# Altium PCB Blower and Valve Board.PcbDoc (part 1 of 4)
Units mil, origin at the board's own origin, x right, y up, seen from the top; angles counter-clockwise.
Board outline 4950 x 3450 mil, 4 copper layers (Top Layer, Signal Layer 1, Signal Layer 2, Bottom Layer), stack 64.4 mil thick; 260 components, 151 nets, 912 pads, 417 vias.
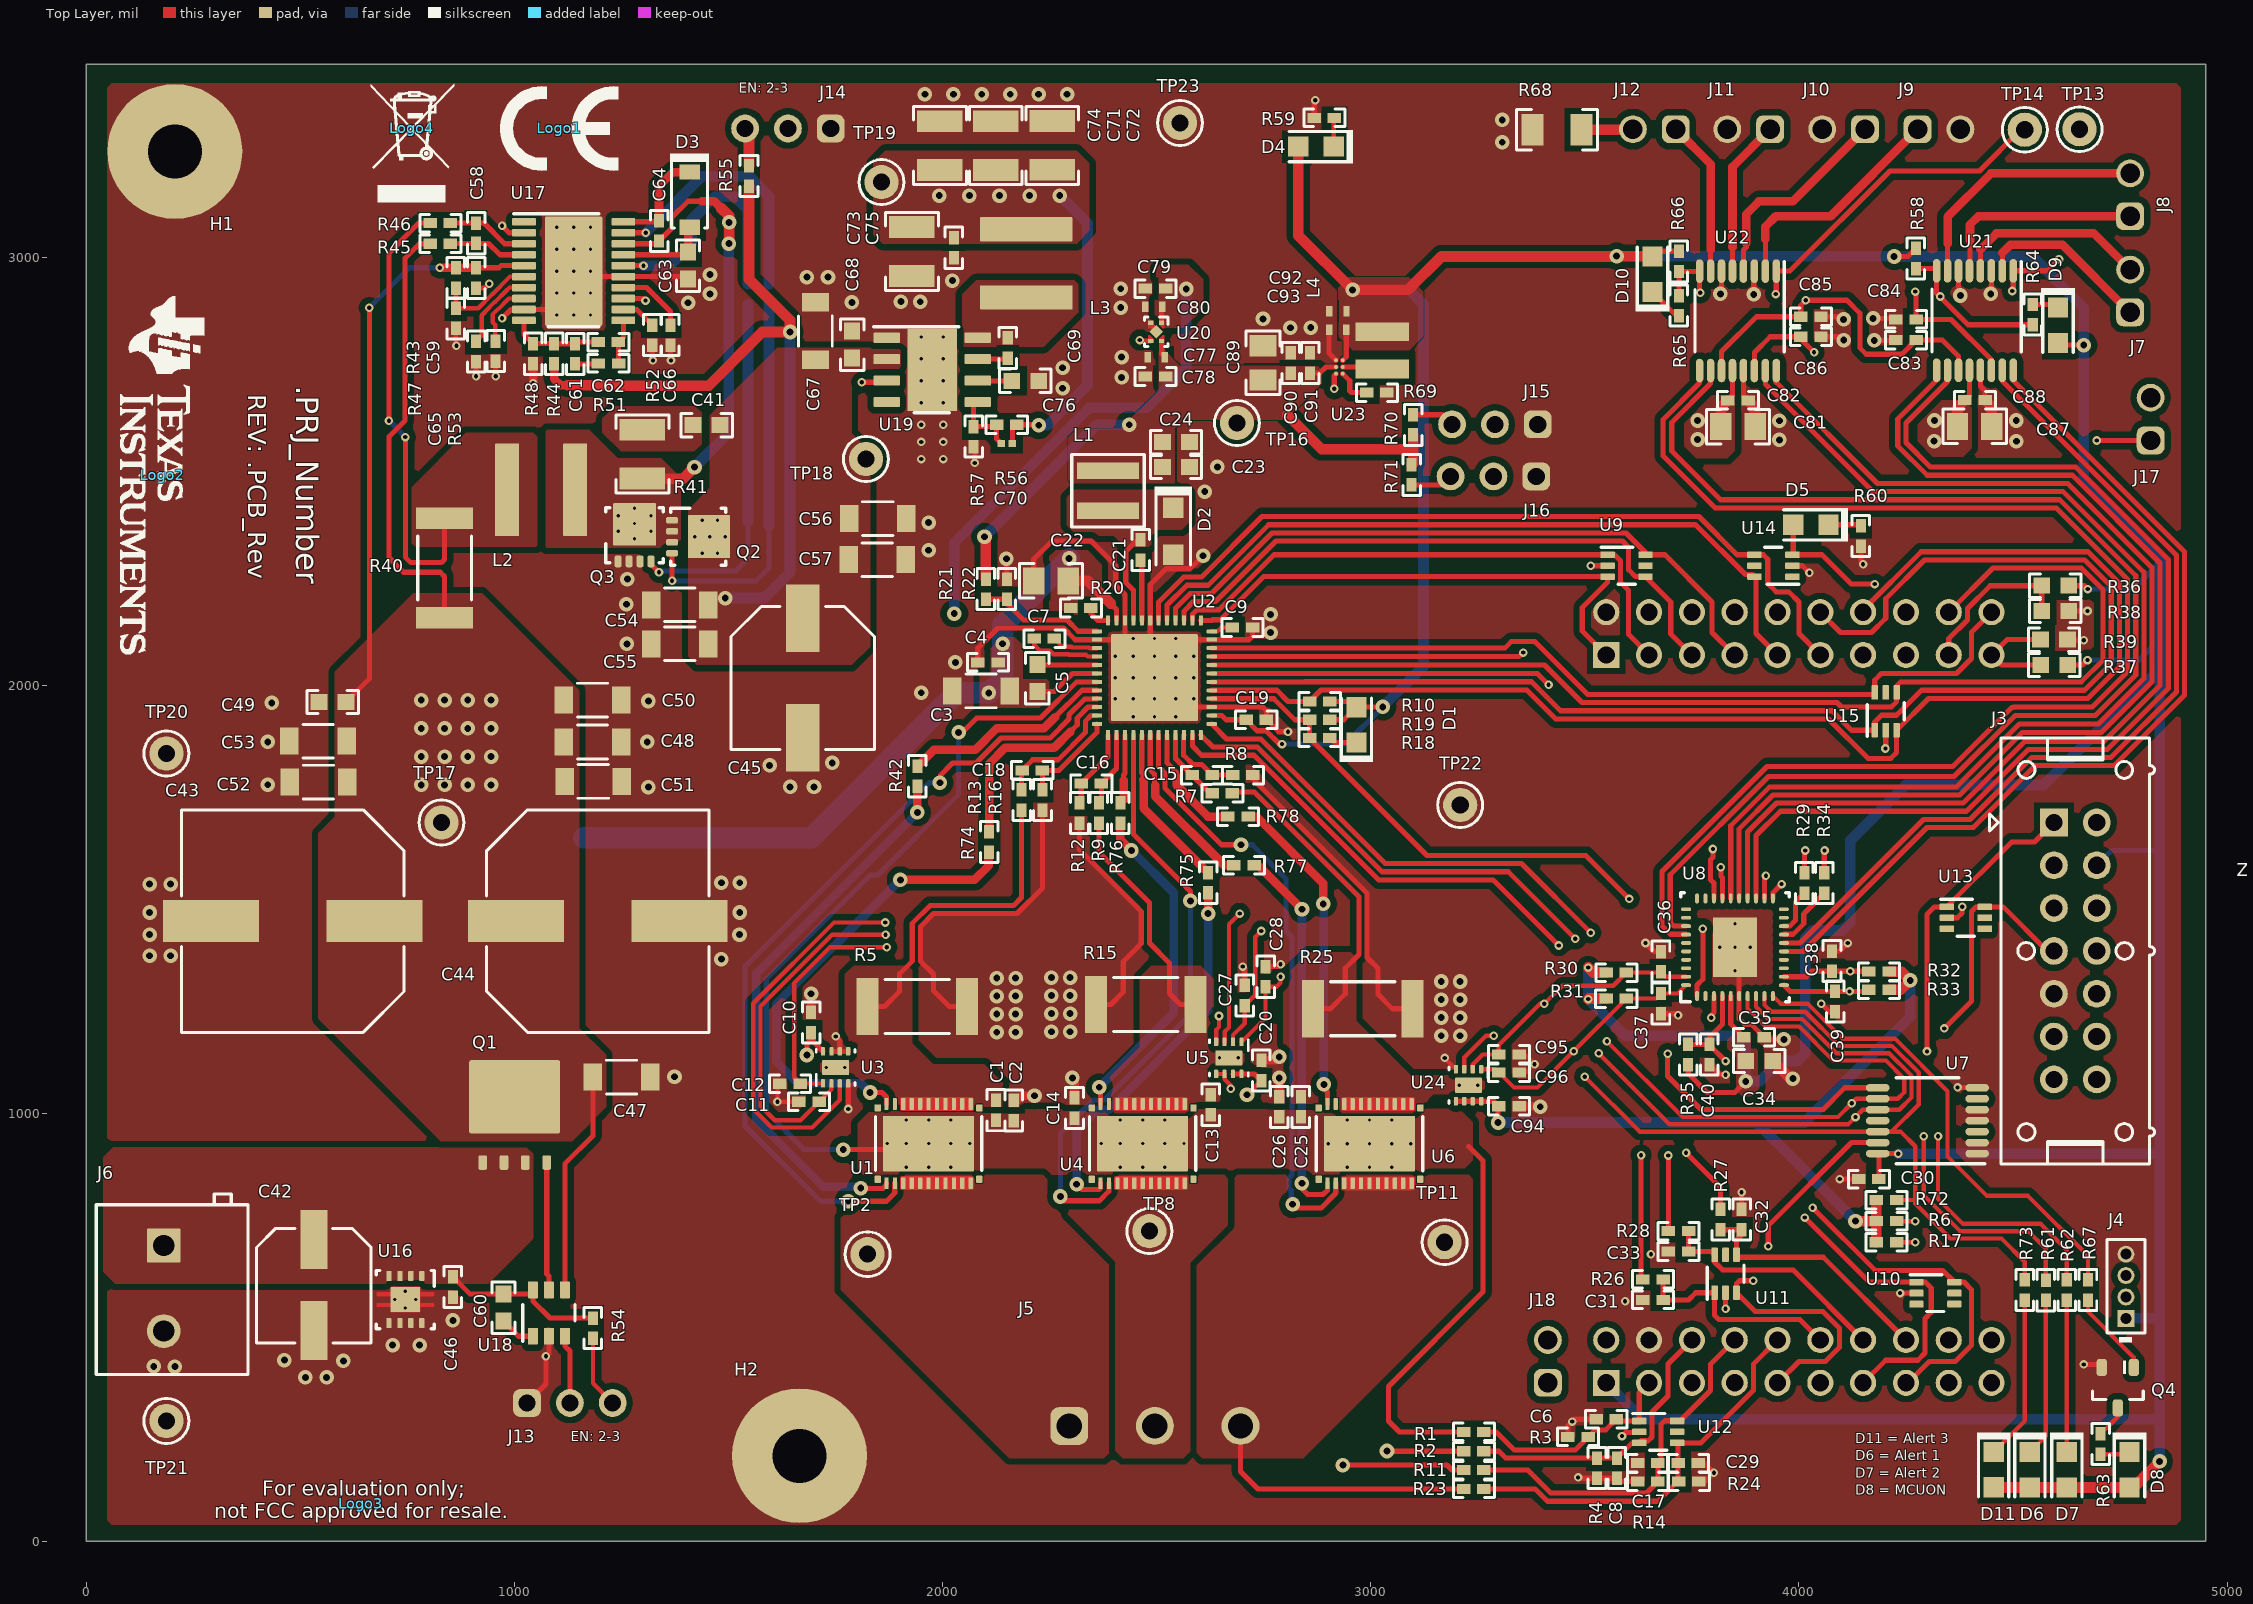
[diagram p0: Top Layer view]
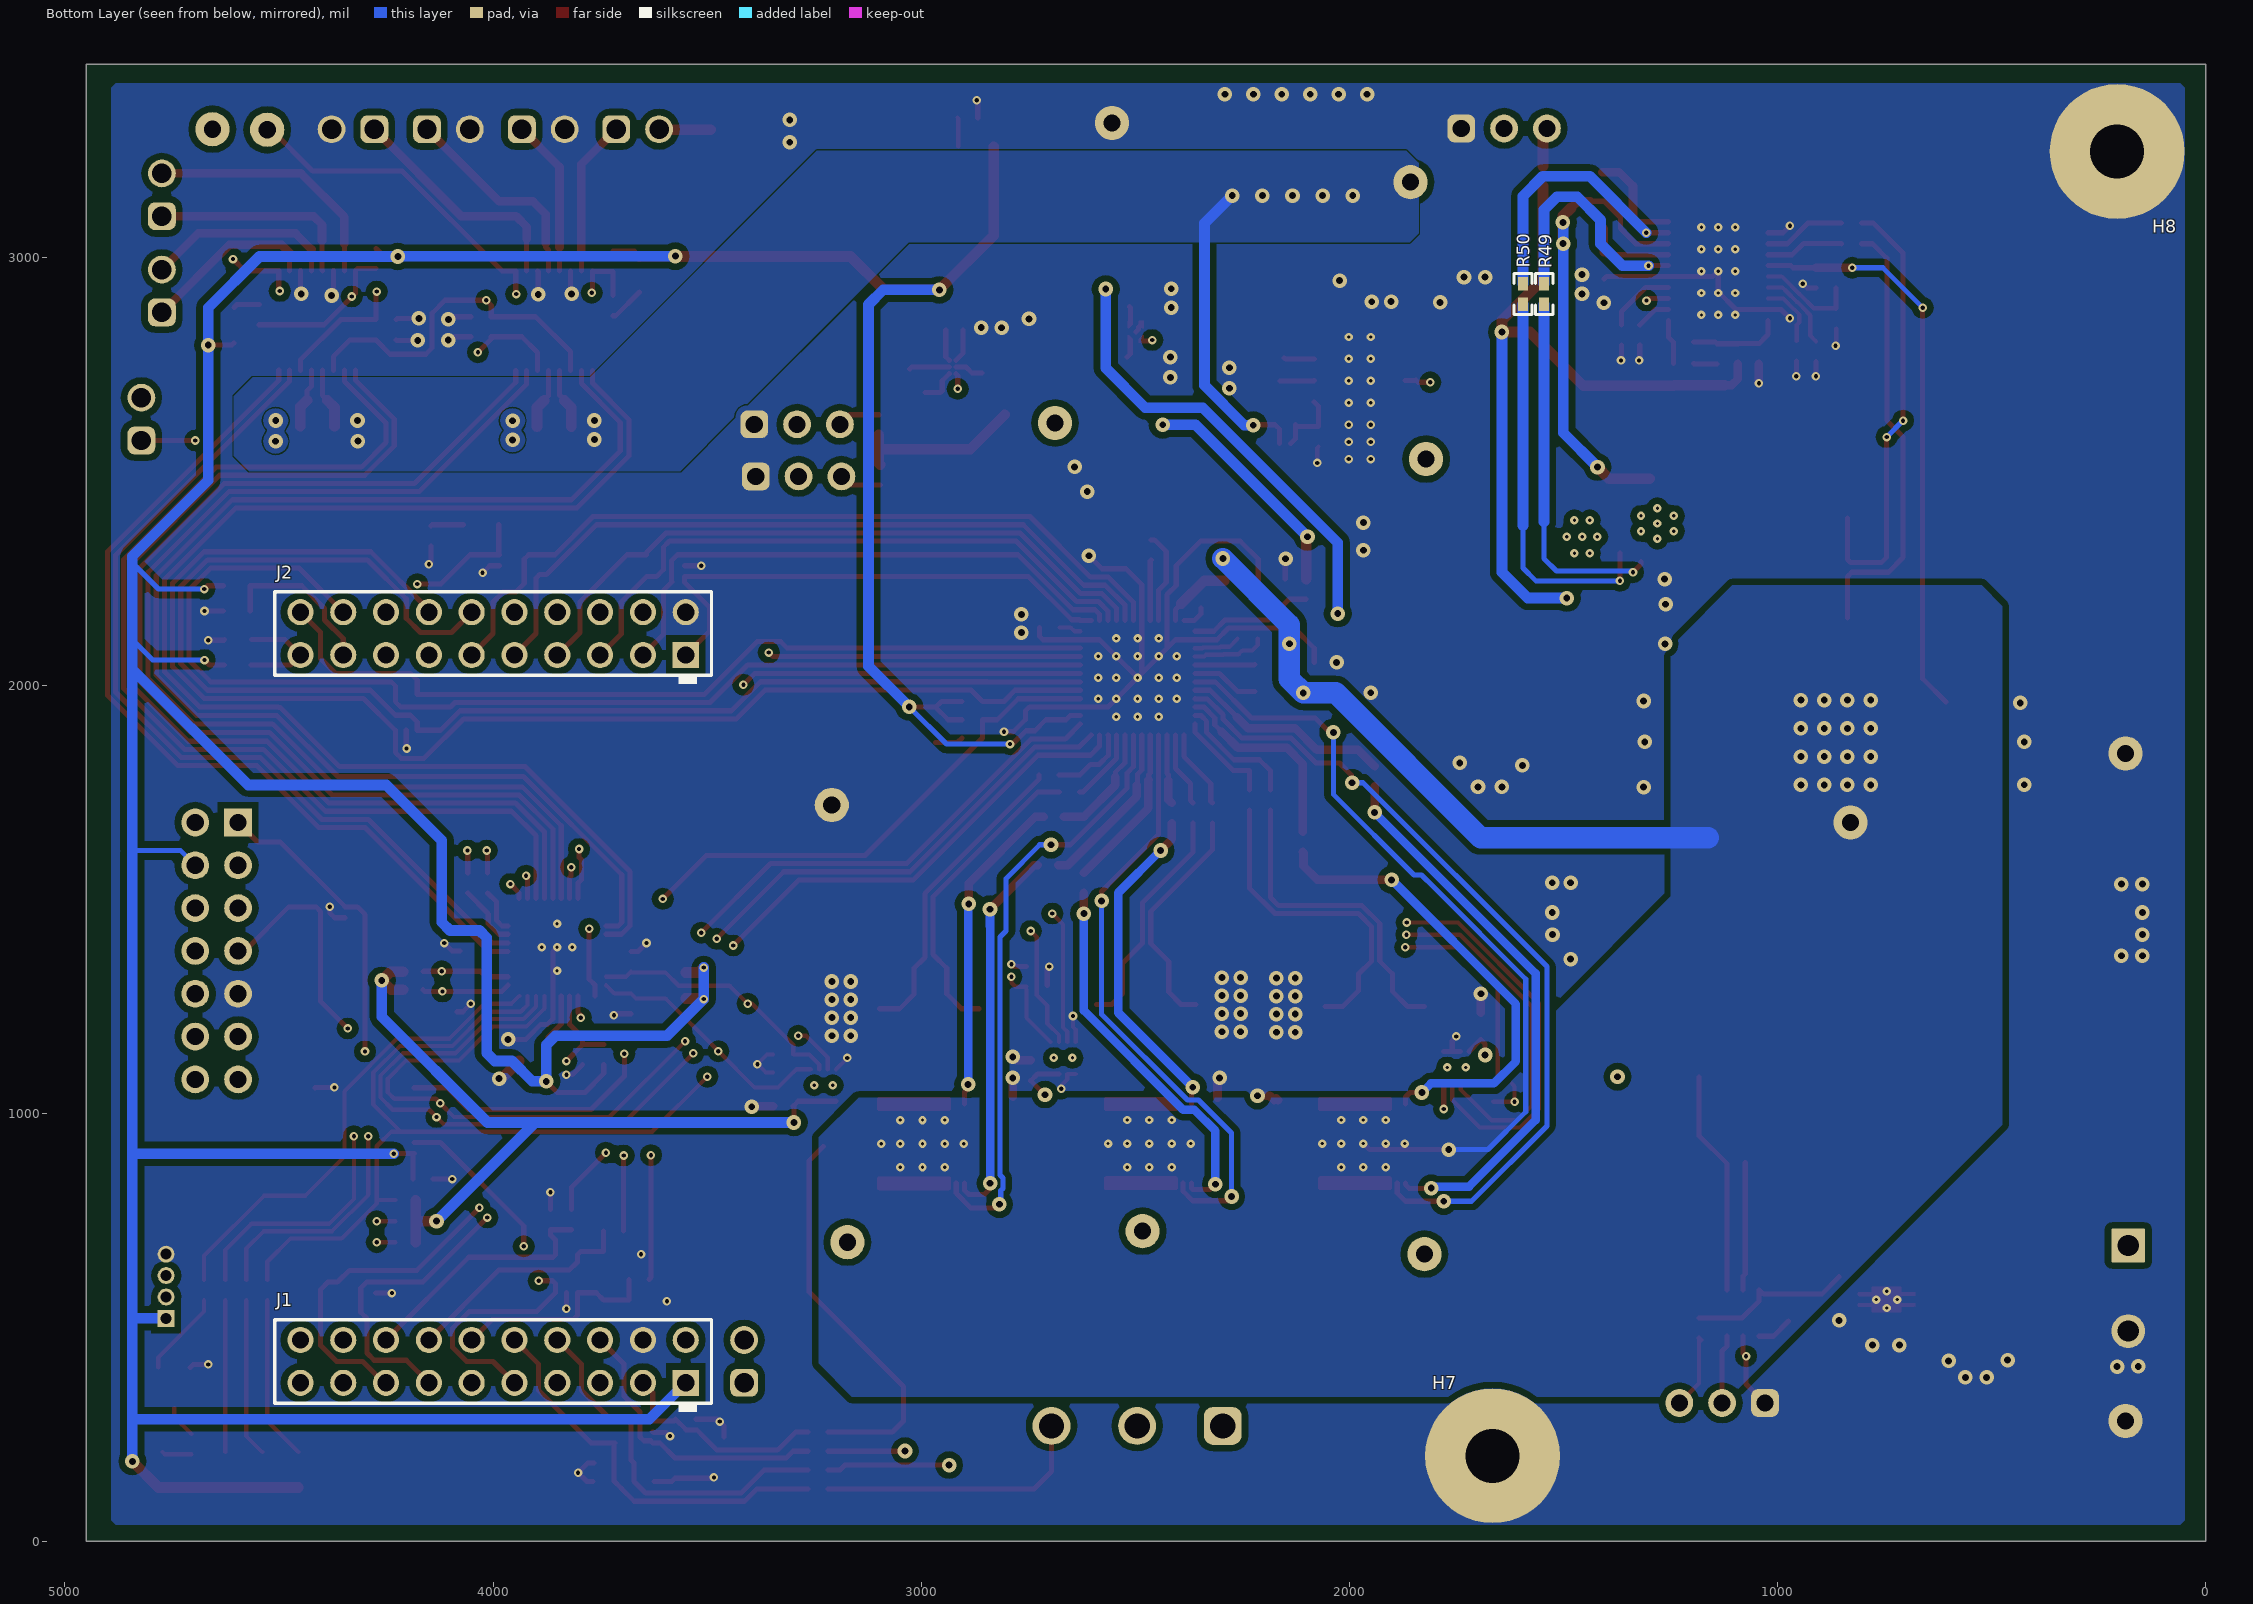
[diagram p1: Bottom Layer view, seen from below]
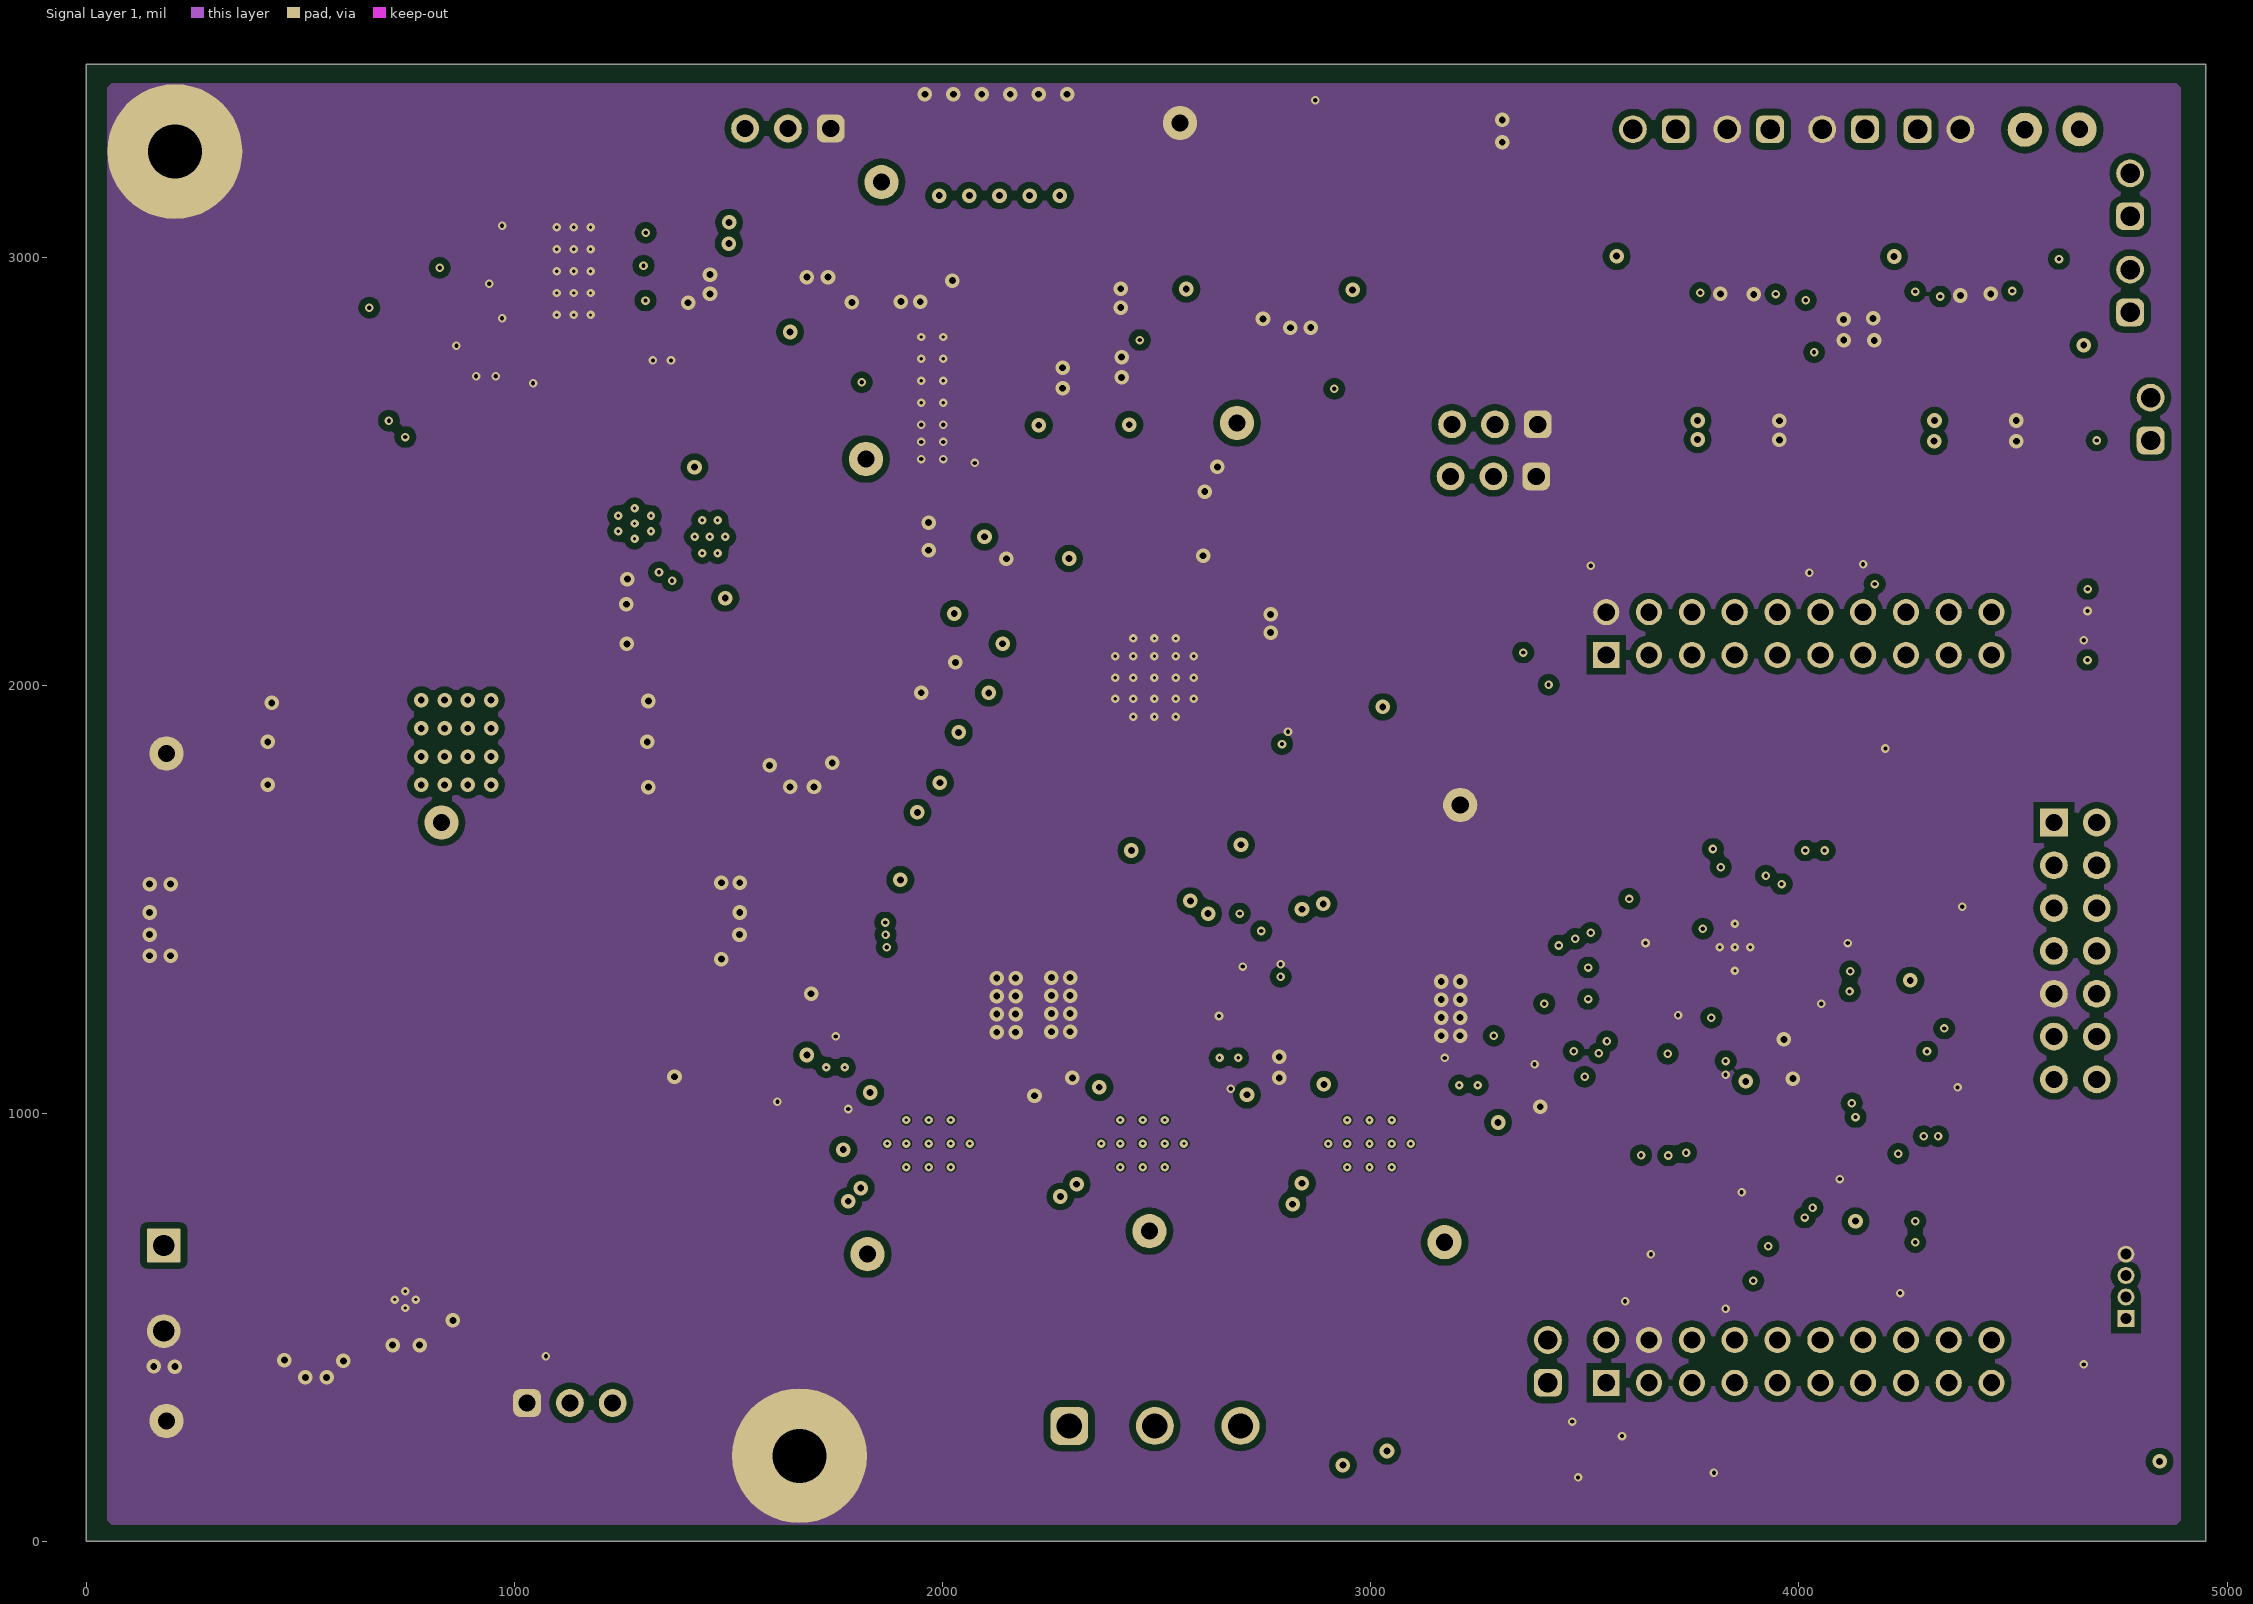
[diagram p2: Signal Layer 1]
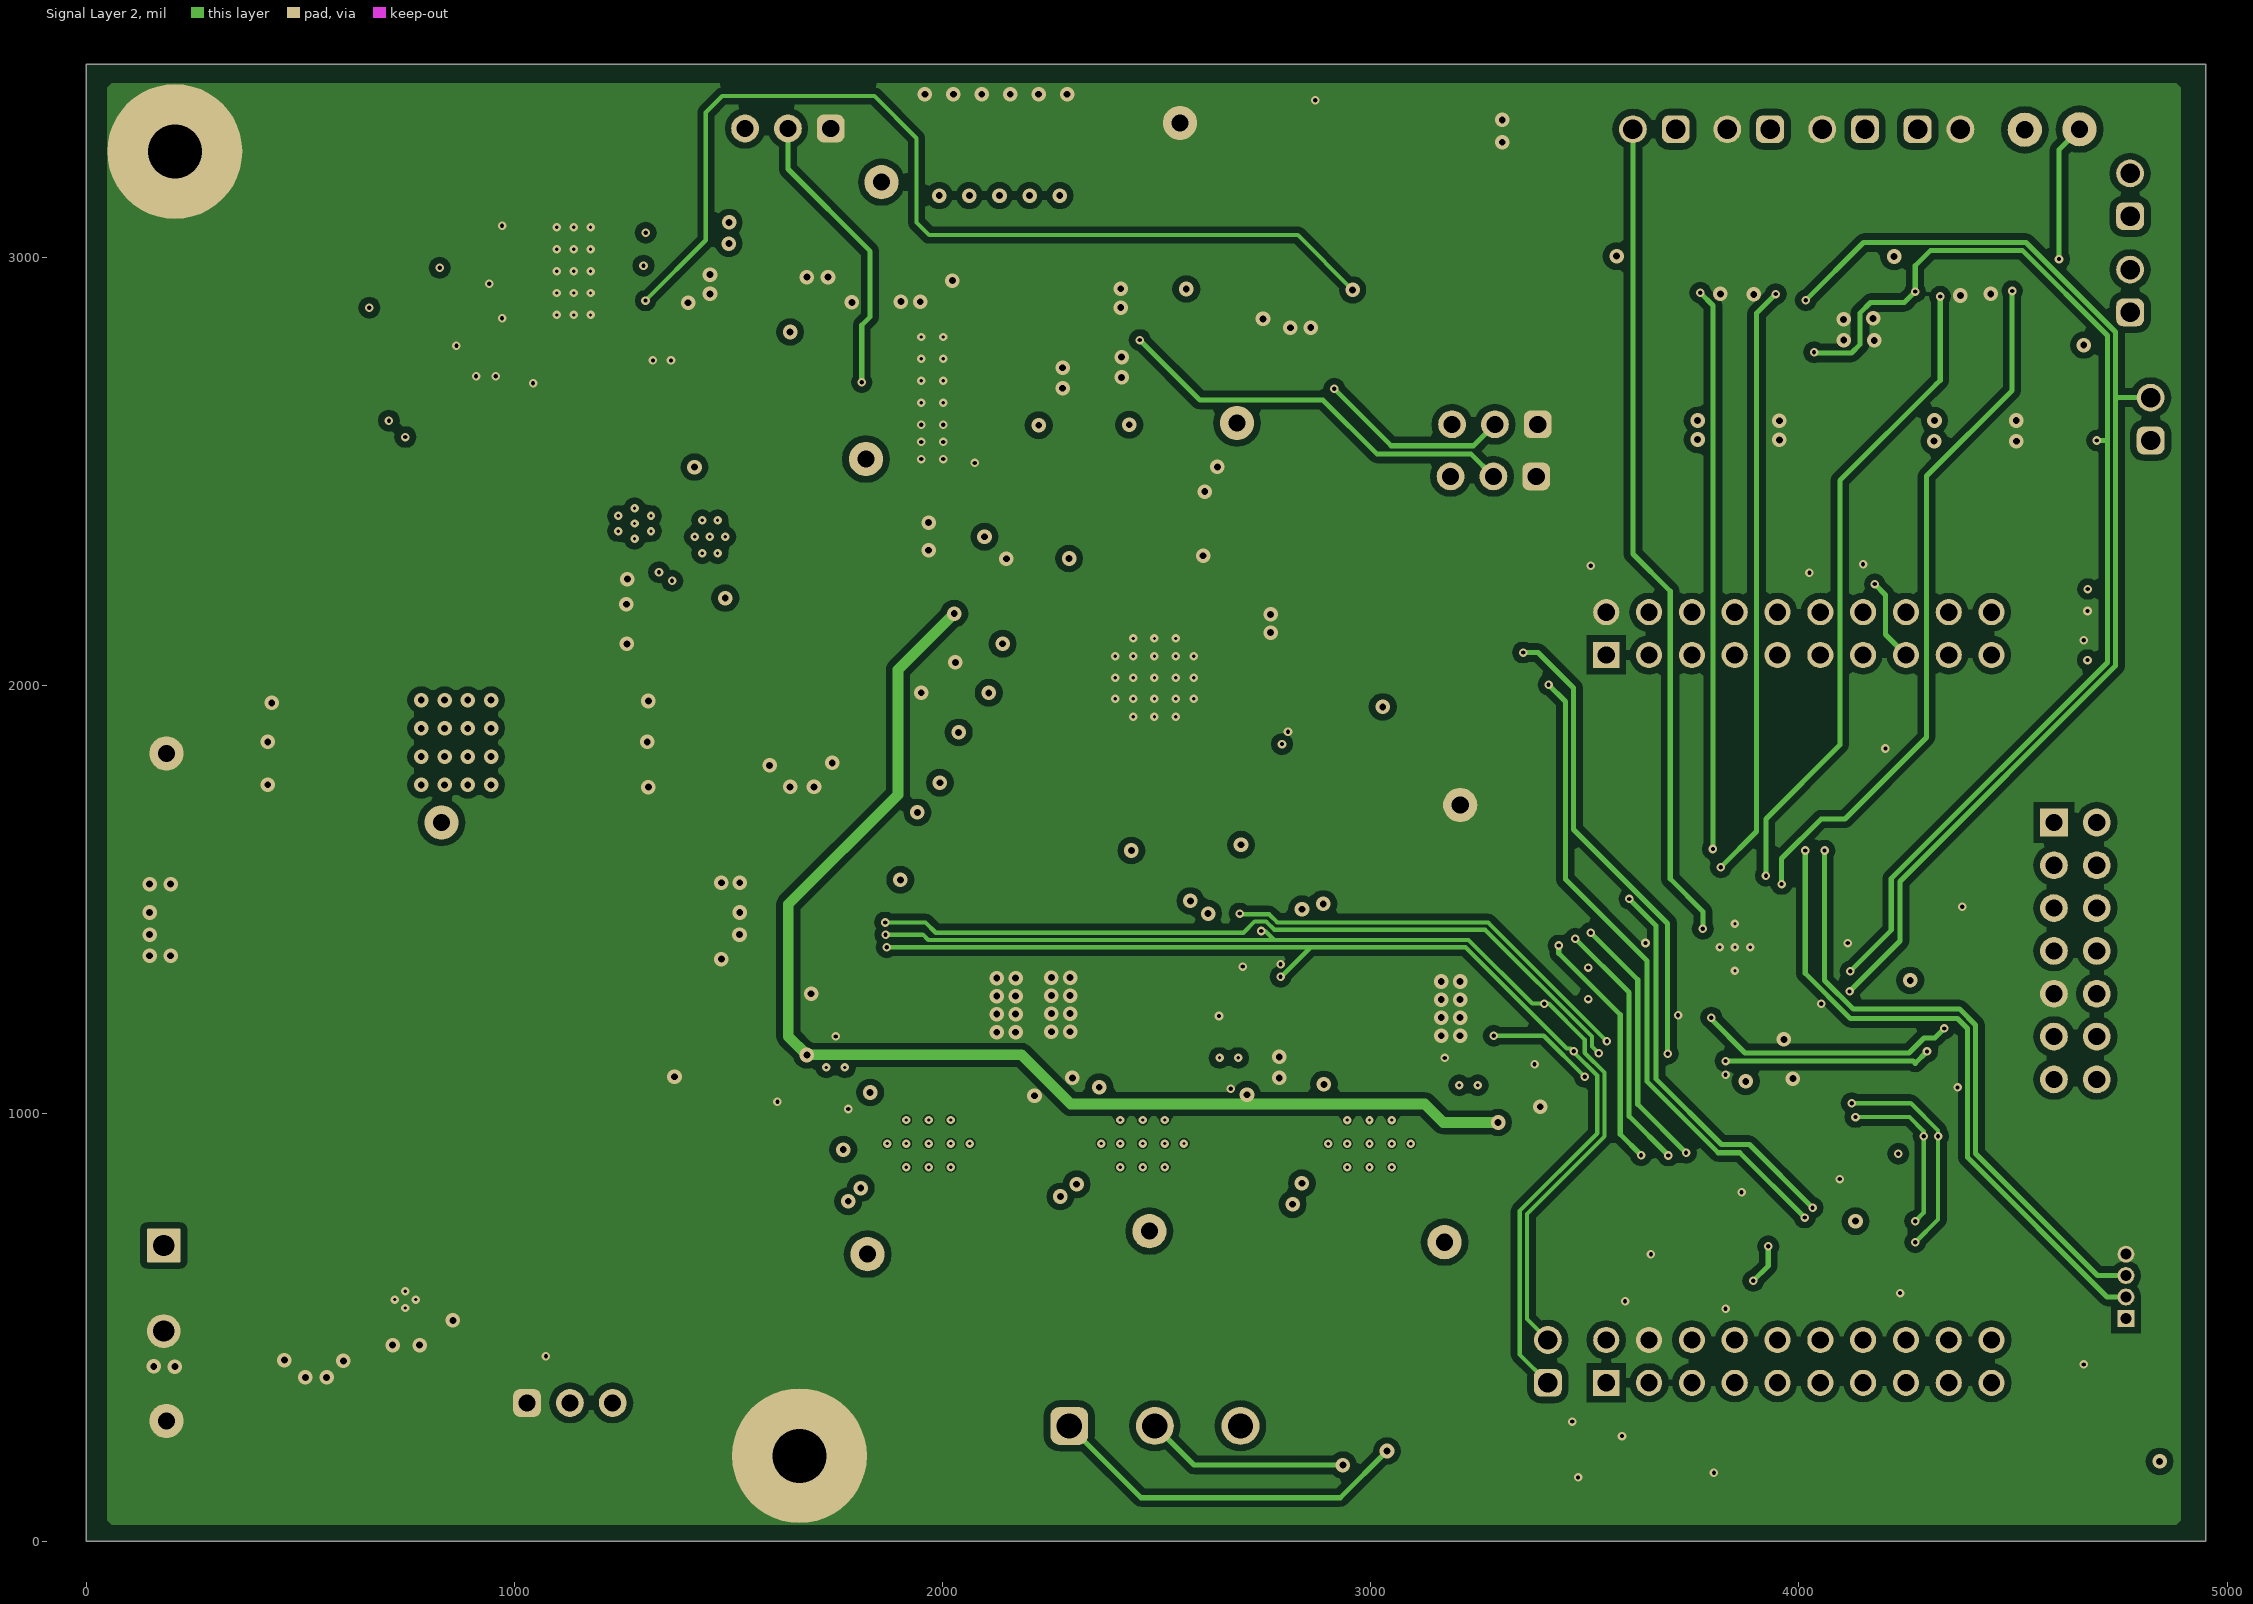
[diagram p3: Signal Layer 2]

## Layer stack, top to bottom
Top Solder: solder mask 0.4, Solder Resist, Dk 3.5
Top Layer: signal copper 2.8
Dielectric 1: prepreg 8, FR-4, Dk 4.2
Signal Layer 1: signal copper 1.4
Dielectric 2: core 40, FR-4, Dk 4.2
Signal Layer 2: signal copper 1.4
Dielectric 3: prepreg 8, FR-4, Dk 4.2
Bottom Layer: signal copper 2.8
Bottom Solder: solder mask 0.4, Solder Resist, Dk 3.5

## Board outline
0,0 4950,0 4950,3450 0,3450

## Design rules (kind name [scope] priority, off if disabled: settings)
AcuteAngle [All] p1: minimum=4.50000000000000E+0001 checktracksonly=FALSE
AssemblyTestPointUsage [All] p1: valid=2
BoardOutlineClearance BoardOutlineClearance_MountingHoles [OnCopper and InComponentClass('Mounting Holes')] p1: gap=40 ignorepadtopadclearanceinfootprint=FALSE
BoardOutlineClearance BoardOutlineClearance_Poly [OnCopper and InPoly] p2: gap=15 ignorepadtopadclearanceinfootprint=FALSE
BoardOutlineClearance [OnCopper and Not InComponentClass('Logo') and not InComponentClass('FiducialMark') and not InRegion(1000,500,4000,800)] p3: gap=15 ignorepadtopadclearanceinfootprint=FALSE
Clearance Clearance_Small_Packages [InComponent('U20') OR InComponent('U23') OR InComponent('U1') Or InComponent('U4') Or InComponent('U6') Or InRegionRelative(2880,2707,2964,2782)] p1: gap=3 ignorepadtopadclearanceinfootprint=FALSE
Clearance Clearance_Keepouts [((IsTrack Or IsArc) And Not InPoly) And IsFree and IsKeepOut vs ((IsTrack Or IsArc) And Not InPoly) And IsFree and IsKeepOut] p2: gap=0 ignorepadtopadclearanceinfootprint=FALSE
Clearance Clearance_Poly [InPolygon] p3: gap=15 ignorepadtopadclearanceinfootprint=FALSE except(0: Arc-Hole Track-Hole SMDPad-Hole THPad-Hole Via-Hole Fill-Hole Poly-Hole Region-Hole Text-Hole)
Clearance [All] p4: gap=7 ignorepadtopadclearanceinfootprint=FALSE
ComponentClearance ComponentClearance_MountingHoles_FiducialMarks [InComponentClass('Mounting Holes') vs InComponentClass('FiducialMark')] p1: gap=50 collisioncheckmode=3 verticalgap=10 showdistances=FALSE
ComponentClearance ComponentClearance_Shunt [InComponentClass('Header') vs InComponentClass('Shunt')] p2: gap=0 collisioncheckmode=3 verticalgap=0 showdistances=FALSE
ComponentClearance ComponentClearance_Logo [InComponentClass('Logo')] p3: gap=20 collisioncheckmode=3 verticalgap=10 showdistances=FALSE
ComponentClearance ComponentClearance_ScrewToNut [(HasFootprint('NY PMS 440 0025 PH')) vs (HasFootprint('Keystone_1902C'))] p4: gap=5 collisioncheckmode=3 verticalgap=10 showdistances=FALSE
ComponentClearance ComponentClearance_MountingHoles [InComponentClass('Mounting Holes')] p5: gap=250 collisioncheckmode=3 verticalgap=100000 showdistances=FALSE
ComponentClearance ComponentClearance_SmallPassives [HasFootprint('0201*') or HasFootprint('0402*') or HasFootprint('0508') or HasFootprint('0603*') or HasFootprint('0612') or HasFootprint('0805*') or HasFootprint('0815*') or HasFootprint('0830*') or HasFootprint('1206*') or HasFootprint('1210*') or HasFootprint('1808*') or HasFootprint('1812*') or HasFootprint('1825*') or HasFootprint('2010*') or HasFootprint('2220*') or HasFootprint('2225*') or HasFootprint('2512*') or HasFootprint('2728*') or HasFootprint('3518*') vs HasFootprint('0201*') or HasFootprint('0402*') or HasFootprint('0508') or HasFootprint('0603*') or HasFootprint('0612') or HasFootprint('0805*') or HasFootprint('0815*') or HasFootprint('0830*') or HasFootprint('1206*') or HasFootprint('1210*') or HasFootprint('1808*') or HasFootprint('1812*') or HasFootprint('1825*') or HasFootprint('2010*') or HasFootprint('2220*') or HasFootprint('2225*') or HasFootprint('2512*') or HasFootprint('2728*') or HasFootprint('3518*')] p6: gap=14.96 collisioncheckmode=3 verticalgap=10 showdistances=FALSE
ComponentClearance ComponentClearance_THtoSMT [IsThruComponent vs IsSMTComponent] p7: gap=20 collisioncheckmode=3 verticalgap=20 showdistances=FALSE
ComponentClearance ComponentClearance_THtoTH [IsThruComponent vs IsThruComponent] p8: gap=20 collisioncheckmode=3 verticalgap=20 showdistances=FALSE
ComponentClearance [All] p9: gap=10 collisioncheckmode=3 verticalgap=10 showdistances=FALSE
DiffPairsRouting [All] p1: maxlimit=100 minlimit=10 mostfreqgap=10 toplayer_minwidth=15 toplayer_maxwidth=15 toplayer_prefwidth=15 midlayer1_minwidth=15 midlayer1_maxwidth=15 midlayer1_prefwidth=15 midlayer2_minwidth=15 midlayer2_maxwidth=15 midlayer2_prefwidth=15 bottomlayer_minwidth=15 bottomlayer_maxwidth=15 bottomlayer_prefwidth=15 maxuncoupledlength=1000
FabricationTestPointUsage TestPointUsage [All] p1: valid=2 allowmultiple=FALSE
FabricationTestpoint Testpoint [All] p1: side=3 testpointundercomponent=TRUE minsize=40 maxsize=100 preferedsize=60 minholesize=0 maxholesize=40 preferedholesize=32 testpointgrid=1 allowsidetop=TRUE allowsidebottom=TRUE usegrid=TRUE gridtolerance=0.01
FanoutControl Fanout_LCC [IsLCC] p1: bgadir=Out bgaviamode=Centered fanoutstyle=Auto fanoutdirection=Alternating viagrid=1 // Fanout_LCC (Default Rule)
FanoutControl Fanout_BGA [IsBGA] p2: bgadir=Out bgaviamode=Centered fanoutstyle=Auto fanoutdirection=Alternating viagrid=1 // Fanout_BGA (Default Rule)
FanoutControl Fanout_Default [All] p4: bgadir=Out bgaviamode=Centered fanoutstyle=Auto fanoutdirection=Alternating viagrid=1 // Fanout_Default (Default Rule)
FanoutControl Fanout_Small [(CompPinCount < 5)] p5: bgadir=Out bgaviamode=Centered fanoutstyle=Auto fanoutdirection=OutThenIn viagrid=1 // Fanout_Small (Default Rule)
HoleSize [All] p1: absolutevalues=TRUE maxlimit=251 minlimit=5 maxpercent=80.000 minpercent=20.000
HoleToHoleClearance [All] p1: gap=7 allowstackedmicrovias=TRUE
MinimumAnnularRing MinimumAnnularRing_ThermalPadVias [IsVia and InAnyComponent] p1: minimumring=5.91
MinimumAnnularRing [All] p2: minimumring=1.5
MinimumSolderMaskSliver MinimumSolderMaskSliver_Logo [InComponentClass('Logo') vs InComponentClass('Logo')] p1: minsoldermaskwidth=0.7
MinimumSolderMaskSliver [All] p2: minsoldermaskwidth=3.94
PlaneClearance [All] p1: clearance=15
PlaneConnect [All] p1: planeconnectstyle=Direct reliefexpansion=10 reliefentries=4 reliefconductorwidth=10 reliefairgap=10
PolygonConnect [All] p1: connectstyle=Direct reliefconductorwidth=10 reliefentries=4 polygonreliefangle="90 Angle" airgapwidth=10
RoutingVias ThermalPadVias [IsVia and InAnyComponent] p1: holewidth=7.87 width=19.68 viastyle="Through Hole" minholewidth=7.87 minwidth=19.68 maxholewidth=12.99 maxwidth=23.62
RoutingVias [All] p2: holewidth=16 width=34 viastyle="Through Hole" minholewidth=6 minwidth=10 maxholewidth=40 maxwidth=65
SilkToBoardRegionClearance [Not ((IsComment or IsDesignator) And (Hide <> 'False')) and not InRegion(1000,500,4000,800)] p1:
SilkToSilkClearance SilkToSilkClearance_Pb-FreeLogo [(HasFootprint('Pb-Free_Overlay_Medium') OR HasFootprint('Pb-Free_Overlay_Small')) vs (HasFootprint('Pb-Free_Overlay_Medium') OR HasFootprint('Pb-Free_Overlay_Small'))] p1: silktosilkclearance=0
SilkToSilkClearance [All] p2: silktosilkclearance=0
SilkToSolderMaskClearance SilkToComponentPadClearance [IsPad and InAnycomponent] p1: minsilkscreentomaskgap=0 clearancetoexposedcopper=TRUE
SilkToSolderMaskClearance "Silk to Solder Mask Opening" [All] p2: minsilkscreentomaskgap=0 clearancetoexposedcopper=FALSE
SolderMaskExpansion [All] p1: expansion=1.97
Width [All] p1: maxlimit=100 minlimit=6 preferedwidth=10 checkconnectedcopper=TRUE
13 further rules are at their usual default settings.

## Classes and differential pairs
component class Logo: Logo2
component class "Mounting Holes": H1 H2
component class Header: J4 J7 J8 J9 J10 J11 J12 J13 J14 J15 J16 J17 J18
component class Hardware: !PCB H1 H2 H7 H8 Logo1 Logo2 Logo3 Logo4 ZZ1 ZZ2 ZZ3 ZZ4
component class AssemblyNote: ZZ1 ZZ2 ZZ3 ZZ4
component class "Valve Drivers and Fault Indicators": C81 C82 C83 C84 C85 C86 C87 C88 D4 D5 D6 D7 D8 D9 D10 D11 J7 J8 J9 J10 J11 J12 Q4 R58 R59 R60 R61 R62 R63 R64 R65 R66 R67 R68 R73 TP13 TP14 TP20 TP21 TP22 TP23 U21 U22
component class "Power Tree": C41 C42 C43 C44 C45 C46 C47 C48 C49 C50 C51 C52 C53 C54 C55 C56 C57 C58 C59 C60 C61 C62 C63 C64 C65 C66 C67 C68 C69 C70 C71 C72 C73 C74 C75 C76 C77 C78 C79 C80 C89 C90 C91 C92 C93 D3 J6 J13 J14 J15 J16 L2 L3 L4 Q1 Q2 Q3 R40 R41 R43 R44 R45 R46 R47 R48 R49 R50 R51 R52 R53 R54 R55 R56 R57 R69 R70 R71 TP17 TP18 TP19 U16 U17 U18 U19 U20 U23
component class "MCU and Connectors": C34 C35 C36 C37 C38 C39 C40 J1 J2 J3 J4 J5 J17 J18 R29 R30 R31 R32 R33 R34 R35 R36 R37 R38 R39 U8 U9 U10 U11 U12 U13 U14 U15
component class "BLDC Motor Driver and TMP Sensors": C1 C2 C3 C4 C5 C6 C7 C8 C9 C10 C11 C12 C13 C14 C15 C16 C17 C18 C19 C20 C21 C22 C23 C24 C25 C26 C27 C28 C29 C30 C31 C32 C33 C94 C95 C96 D1 D2 L1 R1 R2 R3 R4 R5 R6 R7 R8 R9 R10 R11 R12 R13 R14 R15 R16 R17 R18 R19 R20 R21 R22 R23 R24 R25 R26 R27 R28 R42 R72 R74 R75 R76 R77 R78 TP2 TP8 TP11 TP16 U1 U2 U3 U4 U5 U6 U7 U24

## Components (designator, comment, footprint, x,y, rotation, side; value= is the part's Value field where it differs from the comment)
C1 "C1005X7R1H104K050BB" 0402 2124.66,1007.23 r90 top value=0.1uF
C2 "GRM155R71H103KA88D" 0402 2165.99,1006.38 r90 top value=0.01uF
C3 "CL31B106KBHNNNE" 1206_180 2089.75,1986.66 r180 top value=10uF
C4 "C1005X7R1H104K050BB" 0402 2105.79,2052.99 r180 top value=0.1uF
C5 "UMK107AB7105KA-T" 0603 2221.11,2016.51 r90 top value=1uF
C6 "885012105001" 0402 3550,285.43 r180 top value=0.1uF
C7 "C1005X7R1H473K050BB" 0402 2237.55,2108.58 r0 top value=0.047uF
C8 "885012105001" 0402 3575,171.07 r270 top value=0.1uF
C9 "GRM155R70J105MA12D" 0402 2700.22,2134.68 r0 top value=1uF
C10 "GRM155R71E103KA01D" 0402 1692.91,1211.85 r90 top value=0.01uF
C11 "885012005009" 0402 1687.69,1026.98 r180 top value=22pF
C12 "885012005009" 0402 1643.7,1069.07 r180 top value=22pF
C13 "C1005X7R1H104K050BB" 0402 2626.23,1019.86 r90 top value=0.1uF
C14 "GRM155R71H103KA88D" 0402 2308.06,1012.25 r90 top value=0.01uF
C15 "GRM155R61E102KA01D" 0402 2606.23,1789.88 r0 top value=1000pF
C16 "GRM155R61E102KA01D" 0402 2347.24,1770.17 r180 top value=1000pF
C17 "885012105001" 0402 3647.13,182.88 r180 top value=0.1uF
C18 "GRM155R61E102KA01D" 0402 2209.3,1801.02 r0 top value=1000pF
C19 "885012105010" 0402 2732.53,1919.13 r0 top value=0.1uF
C20 "GRM155R71E103KA01D" 0402 2744.34,1099.78 r90 top value=0.01uF
C21 "160R07X104KV4T" 0402_065 2462.58,2315.77 r90 top value=0.1uF
C22 "C2012X5R1H475K125AB" 0805_HV 2252.96,2243.67 r180 top value=4.7uF
C23 "C1608X5R1A226M080AC" 0603 2545.13,2509.38 r0 top value=22uF
C24 "C1608X5R1A226M080AC" 0603 2545.13,2567.37 r0 top value=22uF
C25 "C1005X7R1H104K050BB" 0402 2836.76,1015.13 r90 top value=0.1uF
C26 "GRM155R71H103KA88D" 0402 2786.16,1015.13 r90 top value=0.01uF
C27 "885012005009" 0402 2705.61,1275.27 r90 top value=22pF
C28 "885012005009" 0402 2754.18,1319.03 r90 top value=22pF
C29 "885012105001" 0402 3741.38,182.88 r0 top value=0.1uF
C30 "885012105001" 0402 4163.39,846.46 r180 top value=0.1uF
C31 "GRM155R61C222KA01D" 0402 3659.34,564.06 r180 top value=2200pF
C32 "GRM155R61C222KA01D" 0402 3866.09,751.75 r90 top value=2200pF
C33 "GRM155R61C222KA01D" 0402 3718.74,677.17 r180 top value=2200pF
C34 "CL10A106MQ8NNNC" 0603 3907.48,1122.05 r0 top value=10uF
C35 "885012105010" 0402 3895.06,1177.66 r0 top value=0.1uF
C36 "885012005009" 0402 3677.81,1354.21 r90 top value=22pF
C37 "885012005009" 0402 3677.81,1256.2 r270 top value=22pF
C38 "885012005009" 0402 4077.25,1355.42 r90 top value=22pF
C39 "885012005009" 0402 4084.65,1260.95 r270 top value=22pF
C40 "GRM155R61C102KA01D" 0402 3790.76,1137.4 r270 top value=1000pF
C41 "GRM188R72A471KA01D" 0603 1448.82,2607.16 r180 top value=470pF
C42 "EMZA500ADA470MF80G" CAPSMT_62_F80 531.5,598.86 r270 top value=47uF
C43 "EMVA500ATR331MKE0S" CAPSMT_62_KE0 482.16,1448.95 r180 top value=330uF
C44 "EMVA500ATR331MKE0S" CAPSMT_62_KE0 1194.76,1448.95 r0 top value=330uF
C45 "EEE-FK1H181SP" SM_RADIAL_F 1673.23,2016.51 r270 top value=180uF
C46 "C1005X7R1H104K050BB" 0402 856.3,594.49 r270 top value=0.1uF
C47 "CL31B106KBHNNNE" 1206_180 1250,1084.65 r0 top value=10uF
C48 "CL31B106KBHNNNE" 1206_180 1182.17,1867.31 r0 top value=10uF
C49 "UMK107AB7105KA-T" 0603 575.28,1960.63 r180 top value=1uF
C50 "UMK316BBJ106KL-T" 1206_190 1182.17,1965.15 r0 top value=10uF
C51 "UMK316BBJ106KL-T" 1206_190 1183.91,1775.19 r0 top value=10uF
C52 "UMK316BBJ106KL-T" 1206_190 542.16,1773.62 r180 top value=10uF
C53 "UMK316BBJ106KL-T" 1206_190 541.22,1869.09 r180 top value=10uF
C54 "UMK316BBJ106KL-T" 1206_190 1385.91,2187.66 r180 top value=10uF
C55 "UMK316BBJ106KL-T" 1206_190 1385.91,2096.67 r180 top value=10uF
C56 "UMK316BBJ106KL-T" 1206_190 1848.55,2388.99 r0 top value=10uF
C57 "UMK316BBJ106KL-T" 1206_190 1847.18,2292.98 r0 top value=10uF
C58 "885012205055" 0402 910.3,3055.51 r270 top value=100pF
C59 "GRM155R61H104ME14D" 0402 910.25,2951.22 r270 top value=0.1uF
C60 "UMK107AB7105KA-T" 0603 974.41,546.1 r270 top value=1uF
C61 "GRM155R61A333KA01D" 0402 1141.7,2773.81 r270 top value=0.033uF
C62 "GRM155R71H561KA01D" 0402 1219.2,2801.12 r0 top value=560pF
C63 "EMK107BBJ106MA-T" 0603 1405.39,2979.85 r270 top value=10uF
C64 "C1005X5R1H104K050BB" 0402 1337.59,3061.02 r90 top value=0.1uF
C65 "C1005X5R1A104K050BA" 0402 910.25,2779.31 r270 top value=0.1uF
C66 "C1005X5R1A334K050BB" 0402 1364.11,2817.47 r270 top value=0.33uF
C67 "CL31B106KBHNNNE" 1206_180 1702.86,2827.1 r90 top value=10uF
C68 "C1608X7R1H224K080AB" 0603 1788.61,2795.46 r90 top value=0.22uF
C69 "C1005X7R1H104K050BB" 0402 2151.97,2787.7 r90 top value=0.1uF
C70 "GRM033R71E221KA01D" 0201 2149.77,2564.44 r180 top value=220pF
C71 "GRT32ER61E226KE13L" 1210_270 2124.08,3260.03 r90 top value=22uF
C72 "GRT32ER61E226KE13L" 1210_270 2255.97,3260.85 r90 top value=22uF
C73 "GRT32ER61E226KE13L" 1210_270 1928.09,3012.57 r270 top value=22uF
C74 "GRT32ER61E226KE13L" 1210_270 1993.57,3260.03 r90 top value=22uF
C75 "GRM155R61E105KA12D" 0402 2026.23,3021.65 r270 top value=1uF
C76 "CC0603MRX5R7BB105" 0603 2192.98,2710.82 r0 top value=1uF
C77 "CC0402MRX5R6BB106" 0402_070 2498.83,2766.14 r180 top value=10uF
C78 "GRM155R61A105KE15D" 0402 2497.38,2720.89 r180 top value=1uF
C79 "GRM155R61A105KE15D" 0402 2497.38,2926.14 r180 top value=1uF
C80 "CC0402MRX5R6BB106" 0402_070 2493.19,2883.86 r180 top value=10uF
C81 "GRM21BR61E226ME44L" 0805_HV 3857.63,2603.78 r0 top value=22uF
C82 "GRM155R71E104KE14D" 0402 3857.63,2665 r0 top value=0.1uF
C83 "885012005009" 0402 4250,2806 r180 top value=22pF
C84 "885012005009" 0402 4250,2854.33 r180 top value=22pF
C85 "885012005009" 0402 4027.97,2860.54 r0 top value=22pF
C86 "885012005009" 0402 4027.97,2813.74 r0 top value=22pF
C87 "GRM21BR61E226ME44L" 0805_HV 4410.51,2604.46 r0 top value=22uF
C88 "GRM155R71E104KE14D" 0402 4411.14,2665.68 r0 top value=0.1uF
C89 "C2012X5R1A476M125AC" 0805_HV 2748.27,2752.72 r90 top value=47uF
C90 "C1005X5R1A475K050BC" 0402_065 2813.14,2752.37 r90 top value=4.7uF
C91 "885012105010" 0402 2858.38,2752.37 r90 top value=0.1uF
C92 "CC0402MRX5R6BB106" 0402_070 2923.34,2873.58 r180 top value=10uF
C93 "CC0402MRX5R6BB106" 0402_070 2922.63,2829.85 r180 top value=10uF
C94 "GRM155R71E103KA01D" 0402 3322.64,1016.53 r0 top value=0.01uF
C95 "885012005009" 0402 3322.64,1137.4 r0 top value=22pF
C96 "885012005009" 0402 3322.64,1095.08 r0 top value=22pF
D1 "LTST-C170KRKT" LED_LTST-C170_Red 2966.39,1907.13 r270 top value=Red
D2 "PMEG6010CEH,115" SOD-123F 2538.44,2359.46 r270 top value=60V
D3 "MBR1H100SFT3G" SOD-123FL 1408.95,3134.02 r270 top value=100V
D4 "LTST-C171GKT" LED_LTST-C171 2871.98,3257.87 r0 top value=Green
D5 "LTST-C171GKT" LED_LTST-C171 4027.97,2374.61 r0 top value=Green
D6 "LTST-C170KRKT" LED_LTST-C170_Red 4539.37,167.32 r90 top value=Red
D7 "LTST-C170KRKT" LED_LTST-C170_Red 4625.67,167.32 r90 top value=Red
D8 "LTST-C171GKT" LED_LTST-C171 4772.36,167.32 r90 top value=Green
D9 "LTST-C170KRKT" LED_LTST-C170_Red 4605.3,2840.48 r90 top value=Red
D10 "LTST-C170KRKT" LED_LTST-C170_Red 3658.09,2959.82 r270 top value=Red
D11 "LTST-C170KRKT" LED_LTST-C170_Red 4454.95,167.68 r90 top value=Red
H1 "NY PMS 440 0025 PH" "NY PMS 440 0025 PH" 206.69,3246.49 r0 top
H2 "NY PMS 440 0025 PH" "NY PMS 440 0025 PH" 1665.51,200.05 r0 top
H7 "1902C" Keystone_1902C 1666.03,200.05 r180 bottom
H8 "1902C" Keystone_1902C 206.69,3246.49 r0 bottom
J1 "SSQ-110-03-G-D" Samtec_SSQ-110-03-x-D 4000,420.47 r0 bottom
J2 "SSQ-110-03-G-D" Samtec_SSQ-110-03-x-D 4000,2120.47 r0 bottom
J3 "SBH11-PBPC-D07-ST-BK" CONN_SBH11-PBPC-D07-ST-BK 4645.67,1379.23 r270 top
J4 "850-10-004-10-001101" Preci-dip_850-xx-004-10-001101 4763.78,595.97 r90 top
J5 "691236510003" Wurth_691236510003 2495.7,269.86 r0 top
J6 "ED120/2DS" On-Shore_ED120_2DS 180.71,591.18 r270 top
J7 "61300211121" WURTH_61300211121 4773.62,2920.65 r90 top
J8 "61300211121" WURTH_61300211121 4773.62,3145.4 r90 top
J9 "61300211121" WURTH_61300211121 4327.26,3298.45 r0 top
J10 "61300211121" WURTH_61300211121 4104.36,3298.45 r180 top
J11 "61300211121" WURTH_61300211121 3882.77,3298.45 r180 top
J12 "61300211121" WURTH_61300211121 3662.34,3298.45 r180 top
J13 "TSW-103-07-G-S" TSW-103-07-G-S 1129.34,323.43 r0 top
J14 "TSW-103-07-G-S" TSW-103-07-G-S 1638.59,3300.18 r180 top
J15 "TSW-103-07-G-S" TSW-103-07-G-S 3289.88,2609.24 r180 top
J16 "TSW-103-07-G-S" TSW-103-07-G-S 3286.47,2487.5 r180 top
J17 "61300211121" WURTH_61300211121 4821.51,2621.5 r90 top
J18 "61300211121" WURTH_61300211121 3413.61,420.47 r90 top
L1 "74438356220" WE-MAPI_4020 2386.38,2454.1 r90 top value=22uH
L2 "XAL6060-472MEB" XAL6060 1062.2,2456.3 r0 top value=4.7uH
L3 "XAL6060-333MEB" XAL6060 2195.44,2985.26 r90 top value=33uH
L4 "XFL3012-222MEB" XFL3012 3026.79,2781.74 r90 top value=2.2uH
Logo1 "CE Mark" CE_Mark_5mm 1104.33,3300.18 r0 top
Logo2 "Texas Instruments" TI_Stacked_Overlay_Small 177.17,2490.16 r270 top
Logo3 "FCC disclaimer" FCC_disclaimer_stacked 640.45,88.58 r0 top
Logo4 "WEEE logo" WEEE_Minimum 759.84,3300.18 r0 top
Q1 "CSD18532Q5B" DNK0008A 1000.49,996.06 r90 top value=60V
Q2 "CSD18543Q3A" DNH0008A 1429.03,2346.66 r0 top value=60V
Q3 "CSD18543Q3A" DNH0008A 1280.39,2350.1 r90 top value=60V
Q4 "BC847CLT1G" SOT-23 4744.8,359.15 r270 top value="45 V"
R1 "RC0402FR-0782KL" 0402 3240.75,255.87 r180 top value=82.0k
R2 "RC0402FR-0782KL" 0402 3240.75,210.6 r180 top value=82.0k
R3 "CRCW04024K99FKED" 0402 3484.25,244.09 r0 top value=4.99k
R4 "CRCW04024K99FKED" 0402 3528.35,171.07 r90 top value=4.99k
R5 "CRA2512-FZ-R010ELF" 2512 1940.47,1249.42 r180 top value=0.01
R6 "CRCW04025K10JNED" 0402 4204.51,748.03 r180 top value=5.1k
R7 "RK73H1ETTP10R0F" 0402 2653.23,1747.44 r180 top value=10.0
R8 "RK73H1ETTP10R0F" 0402 2701.23,1789.88 r180 top value=10.0
R9 "RK73H1ETTP10R0F" 0402 2364.96,1701.27 r90 top value=10.0
R10 "CRCW040210K0FKED" 0402 2880.75,1962.04 r0 top value=10.0k
R11 "RC0402FR-0782KL" 0402 3240.75,166.62 r180 top value=82.0k
R12 "RK73H1ETTP10R0F" 0402 2319.68,1701.27 r90 top value=10.0
R13 "RK73H1ETTP10R0F" 0402 2184.3,1731.92 r90 top value=10.0
R14 "CRCW04024K99FKED" 0402 3647.13,139.95 r0 top value=4.99k
R15 "CRA2512-FZ-R010ELF" 2512 2474.66,1254.11 r0 top value=0.01
R16 "RK73H1ETTP10R0F" 0402 2233.23,1731.92 r90 top value=10.0
R17 "CRCW04025K10JNED" 0402 4204.51,698.82 r180 top value=5.1k
R18 "CRCW0402470RJNED" 0402 2880.75,1876.74 r0 top value=470
R19 "CRCW040210K0FKED" 0402 2880.75,1919.13 r0 top value=10.0k
R20 "RMCF0402FT100K" 0402 2322.83,2180.26 r180 top value=100k
R21 "CRCW040249K9FKED" 0402 2101.03,2224.25 r90 top value=49.9k
R22 "CRCW040211K8FKED" 0402 2149.89,2224.25 r270 top value=11.8k
R23 "RC0402FR-0782KL" 0402 3240.75,122.63 r180 top value=82.0k
R24 "CRCW04024K99FKED" 0402 3742.76,139.95 r180 top value=4.99k
R25 "CRA2512-FZ-R010ELF" 2512 2980.96,1244.27 r180 top value=0.01
R26 "CRCW040256R2FKED" 0402 3659.34,612.11 r0 top value=56.2
R27 "CRCW040256R2FKED" 0402 3816.93,751.75 r270 top value=56.2
R28 "CRCW040256R2FKED" 0402 3718.74,724.74 r0 top value=56.2
R29 "CRCW0402102RFKED" 0402 4012.84,1538 r90 top value=102
R30 "CRCW04023K30JNED" 0402 3573.62,1328.74 r180 top value=3.3k
R31 "CRCW04023K30JNED" 0402 3573.31,1268.01 r180 top value=3.3k
R32 "CRCW04023K30JNED" 0402 4186.99,1330.82 r0 top value=3.3k
R33 "CRCW04023K30JNED" 0402 4186.99,1288.47 r0 top value=3.3k
R34 "CRCW0402102RFKED" 0402 4059.11,1538 r90 top value=102
R35 "CRCW040247K0JNED" 0402 3741.38,1137.4 r90 top value=47k
R36 "CRCW060335K7FKEA" 0603 4598.69,2232.25 r0 top value=35.7k
R37 "CRCW060335K7FKEA" 0603 4596.46,2047.24 r0 top value=35.7k
R38 "CRCW060335K7FKEA" 0603 4598.69,2173.23 r180 top value=35.7k
R39 "CRCW060335K7FKEA" 0603 4595.67,2106.3 r180 top value=35.7k
R40 "PMR100HZPFU8L00" 2512 836.61,2273.62 r90 top value=0.008
R41 "RC1210JR-078R2L" 1210 1298.94,2539.47 r90 top value=8.2
R42 "CRCW04020000Z0EDHP" 0402 1941.19,1787.15 r270 top value=0
R43 "MCR01MZPF4992" 0402 863.01,2951.22 r90 top value=49.9k
R44 "ERJ2RKF3902X" 0402 1092.52,2774 r270 top value=39.0k
R45 "CRCW0402100RFKED" 0402 826.82,3031.03 r180 top value=100
R46 "CRCW0402100RFKED" 0402 826.82,3079.18 r180 top value=100
R47 "RC0402FR-0714KL" 0402 863.01,2856.72 r90 top value=14.0k
R48 "CRCW04023K65FKED" 0402 1043.31,2774 r90 top value=3.65k
R49 "CRCW04020000Z0EDHP" 0402 1545.28,2913.39 r270 bottom value=0
R50 "CRCW04020000Z0EDHP" 0402 1594.49,2913.39 r270 bottom value=0
R51 "CRCW040223K2FKED" 0402 1219.34,2751.44 r180 top value=23.2k
R52 "CRCW0402140KFKED" 0402 1321.88,2817.47 r90 top value=140k
R53 "CRCW040236K5FKED" 0402 955.71,2780.07 r90 top value=36.5k
R54 "CRCW0402100KJNED" 0402 1183.21,498.1 r90 top value=100k
R55 "CRCW0402100KJNED" 0402 1547.7,3189.17 r270 top value=100k
R56 "RMCF0402FT100K" 0402 2149.77,2608.27 r0 top value=100k
R57 "CRCW04029K09FKED" 0402 2072.27,2580.38 r90 top value=9.09k
R58 "CRCW040210K0JNED" 0402 4273.35,2996.38 r90 top value=10k
R59 "CRCW0402470RJNED" 0402 2891.58,3325.03 r0 top value=470
R60 "CRCW0402470RJNED" 0402 4144.77,2348.54 r90 top value=470
R61 "CRCW0402470RJNED" 0402 4576.77,586.76 r270 top value=470
R62 "CRCW0402470RJNED" 0402 4625.67,587.09 r270 top value=470
R63 "CRCW0402330RJNED" 0402 4704.72,227.48 r270 top value=330
R64 "CRCW0402470RJNED" 0402 4546.24,2865.48 r90 top value=470
R65 "CRCW0402470RJNED" 0402 3719.84,2886.46 r270 top value=470
R66 "CRCW040210K0JNED" 0402 3719.84,2989.81 r90 top value=10k
R67 "CRCW0402100KJNED" 0402 4675.15,587.09 r270 top value=100k
R68 "CSR1206FKR330" 1206 3435.04,3297.24 r0 top value=0.33
R69 "CRCW0402267KFKED" 0402 3014.24,2683.14 r180 top value=267k
R70 "CRCW0402100KJNED" 0402 3098.96,2608.03 r270 top value=100k
R71 "CRCW0402100KJNED" 0402 3095.55,2491.19 r90 top value=100k
R72 "CRCW04025K10JNED" 0402 4204.51,797.24 r180 top value=5.1k
R73 "CRCW0402470RJNED" 0402 4527.56,587.09 r270 top value=470
R74 "CRCW04020000Z0EDHP" 0402 2108.51,1633.86 r270 top value=0
R75 "CRCW04020000Z0EDHP" 0402 2619.97,1538.38 r270 top value=0
R76 "CRCW04020000Z0EDHP" 0402 2415,1701.27 r270 top value=0
R77 "CRCW04020000Z0EDHP" 0402 2703.91,1579.23 r0 top value=0
R78 "CRCW04020000Z0EDHP" 0402 2690.13,1692.91 r0 top value=0
TP2 "5117" Keystone5117 1824.72,670.97 r0 top
TP8 "5117" Keystone5117 2482.92,724.74 r0 top
TP11 "5117" Keystone5117 3172.46,698.92 r0 top
TP13 "5117" Keystone5117 4655.51,3298.45 r0 top
TP14 "5117" Keystone5117 4527.56,3297.24 r90 top
TP16 "5000" Keystone5000 2687.45,2612.22 r90 top
TP17 "5000" Keystone5000 829.49,1679.23 r0 top
TP18 "5000" Keystone5000 1820.87,2528.08 r0 top
TP19 "5000" Keystone5000 1857.21,3174.91 r0 top
TP20 "5001" Keystone5001 187.01,1840.55 r90 top
TP21 "5001" Keystone5001 187.01,281.5 r0 top
TP22 "5001" Keystone5001 3208.93,1720.11 r90 top
TP23 "5001" Keystone5001 2554.37,3313.22 r90 top
U1 "CSD88584Q5DC" DMM0022A 1967.18,929.31 r90 top
U2 "DRV8323RSRGZR" RGZ0048A 2494.73,2017.56 r0 top
U3 "TMP1075DSGT" DSG0008A 1750,1107.09 r90 top
U4 "CSD88584Q5DC" DMM0022A 2467.18,929.31 r90 top
U5 "TMP1075DSGT" DSG0008A 2668.47,1129.31 r270 top
U6 "CSD88584Q5DC" DMM0022A 2997.05,929.11 r90 top
U7 "SN74HC21PW" PW0014A_N 4300.2,982.76 r180 top
U8 "MSP430FR2155TRHAR" RHA0040E 3850.63,1387.92 r90 top
U9 "TPD4E1U06DCKR" DCK0006A_N 3597.44,2279.01 r0 top
U10 "TPD4E1U06DCKR" DCK0006A_N 4318.9,580.08 r0 top
U11 "TPD4E1U06DCKR" DCK0006A_N 3828.74,625.08 r90 top
U12 "TPD4E1U06DCKR" DCK0006A_N 3671.26,255.91 r0 top
U13 "TPD4E1U06DCKR" DCK0006A_N 4389.76,1456.63 r0 top
U14 "TPD4E1U06DCKR" DCK0006A_N 3940.35,2279.01 r180 top
U15 "TPD4E1U06DCKR" DCK0006A_N 4202.76,1938.98 r90 top
U16 "TVS3301DRBR" DRB0008A 745.08,564.96 r270 top
U17 "LM5122MHX/NOPB" PWP0020A_N 1138.29,2967.06 r0 top
U18 "LM74700QDBVTQ1" DBV0006A_N 1080.24,533.49 r90 top
U19 "LMR33630ADDAR" DDA0008J 1975.8,2736.41 r0 top
U20 "TPS7A0233PDQNR" DQN0004A 2498.7,2825.2 r270 top
U21 "DRV8847SPWR" PW0016A_N 4411.14,2851.7 r270 top
U22 "DRV8847SPWR" PW0016A_N 3857.63,2851.03 r270 top
U23 "TPS62840YBGR" YBG0006AJAN 2926.65,2743.13 r0 top
U24 "TMP1075DSGT" DSG0008A 3228.35,1065.55 r270 top
ZZ1 "This Assembly Note is for PCB labels only" AssemblyNoteLabel 5567.83,247.49 r90 top
ZZ2 "These assemblies are ESD sensitive, ESD precautions shall be observed." AssemblyNote 5390.66,2727.8 r90 top
ZZ3 "These assemblies must be clean and free from flux and all contaminants. Use of no clean flux is not acceptable." AssemblyNote 5213.5,1172.69 r90 top
ZZ4 "These assemblies must comply with workmanship standards IPC-A-610 Class 2, unless otherwise specified." AssemblyNote 5036.34,1507.33 r90 top

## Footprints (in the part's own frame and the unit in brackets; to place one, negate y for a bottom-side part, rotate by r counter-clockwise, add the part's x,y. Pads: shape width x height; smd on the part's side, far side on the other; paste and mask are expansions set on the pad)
0201 [mm] "Data from Kemet datasheet CC101_COM dated 7/28/11"
  rect 0.46x0.42 smd mask+0.048: 1(-0.33,0) 2(0.33,0)
  body extent -0.31,-0.16 0.31,0.16, height 0.26
0402 [mm] "0402 from SM-752 data"
  rect 0.8x0.6 smd: 1(-0.6,0) 2(0.6,0)
  silkscreen extent -1.22,-0.52 1.22,0.52, body extent -0.55,-0.3 0.55,0.3, height 0.6
0402_065 [mm] "0402"
  rect 0.8x0.6 smd: 1(-0.6,0) 2(0.6,0)
  silkscreen extent -1.22,-0.52 1.22,0.52, body extent -0.55,-0.3 0.55,0.3, height 0.65
0402_070 [mil] "SMD, 2-Leads, Body 1.2x0.7mm, Height 0.7mm"
  rect 15x24 smd: 1(-20,0) 2(20,0)
  body extent -24,-14 24,14, height 28
0603 [mm] "0603 from SM-752 data"
  rect 1x0.95 smd: 1(-0.8,0) 2(0.8,0)
  silkscreen extent -1.52,-0.69 1.52,0.69, body extent -0.87,-0.47 0.87,0.47, height 1
0805_HV [mil] "0805 with 30mil clearance between pads"
  rect 50x63 smd: 1(-40,0) 2(40,0)
  silkscreen extent -74,-40 74,40, body extent -43,-29 43,29, height 57
1206 [mm] "1206 from SM-752 data"
  rect 1.3x1.85 smd: 1(-1.45,0) 2(1.45,0)
  silkscreen extent -2.4,-1.21 2.4,1.21, body extent -1.7,-0.9 1.7,0.9, height 1.35
1206_180 [mm] "1206_180"
  rect 1.1x1.6 smd: 1(-1.7,0) 2(1.7,0)
  silkscreen extent -0.9,-1 0.9,1, body extent -1.75,-0.95 1.75,0.95, height 1.8
1206_190 [mm] "1206_190"
  rect 1.1x1.6 smd: 1(-1.7,0) 2(1.7,0)
  silkscreen extent -0.9,-1 0.9,1, body extent -1.75,-0.95 1.75,0.95, height 1.9
1210 [mm] "1210 from SM-752 data"
  rect 1.3x2.7 smd: 1(-1.45,0) 2(1.45,0)
  silkscreen extent -2.32,-1.57 2.32,1.57, body extent -1.7,-1.35 1.7,1.35, height 1.35
1210_270 [mm] "1210"
  rect 1.3x2.7 smd: 1(-1.45,0) 2(1.45,0)
  silkscreen extent -2.32,-1.57 2.32,1.57, body extent -1.7,-1.35 1.7,1.35, height 2.7
2512 [mm] "Chip Resistor, Body 6.3x3.2mm, IPC Medium Density"
  rect 1.3x3.4 smd: 1(-2.95,0) 2(2.95,0)
  silkscreen extent -1.9,-1.6 1.9,1.6, body extent -3.22,-1.67 3.22,1.67, height 0.71
AssemblyNote [mil] "Assembly Note"
AssemblyNoteLabel [mil] "Assembly Note for PCB Labels"
CAPSMT_62_F80 [mm] "6.3 x 7.7mm:  Chemi-Con F80"
  rect 3.5x1.6 smd: 1(-2.7,0) 2(2.7,0)
  silkscreen extent -3.36,-3.4 3.44,3.4, body extent -3.4,-3.4 3.44,3.4, height 8
CAPSMT_62_KE0 [mm] "12.5 x 13.5mm:  Chemi-Con KE0"
  rect 5.7x2.5 smd: 1(-4.85,0) 2(4.85,0)
  silkscreen extent -6.6,-6.6 6.6,6.6, body extent -6.6,-6.6 6.6,6.6, height 14
CE_Mark_5mm [mil] "Minimum text height for CE Mark"
  silkscreen extent -138,-98 138,98
CONN_SBH11-PBPC-D07-ST-BK [mm] "Sullins recommended land pattern"
  rect 1.65x1.65 hole 1.016 mask+0: 1(-7.62,-1.27)
  round 1.65 hole 1.016 mask+0: 2(-7.62,1.27) 3(-5.08,-1.27) 4(-5.08,1.27) 5(-2.54,-1.27) 6(-2.54,1.27) 7(0,-1.27) 8(0,1.27) 9(2.54,-1.27) 10(2.54,1.27) 11(5.08,-1.27) 12(5.08,1.27) 13(7.62,-1.27) 14(7.62,1.27)
  silkscreen extent -12.64,-5.08 12.64,4.7, body extent -12.64,-4.4 12.64,4.7, height 9.12
DBV0006A_N [mm] "SOT23, 6-Leads, Body 2.9x1.6mm, Pitch 0.95mm, Lead Span 2.8mm, IPC Medium Density"
  rrect17% 1x0.6 smd: 1(-1.375,0.95) 2(-1.375,0) 3(-1.375,-0.95) 4(1.375,-0.95) 5(1.375,0) 6(1.375,0.95)
  silkscreen extent -1.68,-1.55 0.5,1.55, body extent -1.42,-1.46 1.42,1.46, height 1.12
DCK0006A_N [mm] "SOT23, 6-Leads, Body 2x1.3mm, Pitch 0.65mm, Lead Span 2.1mm, IPC Medium Density"
  rrect25% 0.85x0.4 smd: 1(-1.125,0.65) 2(-1.125,0) 3(-1.125,-0.65) 4(1.125,-0.65) 5(1.125,0) 6(1.125,0.65)
  silkscreen extent -1.5,-1.09 0.51,1.09, body extent -1.14,-1 1.14,1, height 0.95
DDA0008J [mm] "SOIC, 8-Leads, Body 4.9x3.9mm, Pitch 1.27mm, Exposed Pad"
  rrect14% 1.55x0.6 smd: 1(-2.7,1.905) 2(-2.7,0.635) 3(-2.7,-0.635) 4(-2.7,-1.905) 5(2.7,-1.905) 6(2.7,-0.635) 7(2.7,0.635) 8(2.7,1.905)
  rrect4% 2.95x4.9 smd paste-1.5 mask-1.5: 9(0,0)
  silkscreen extent -3.47,-2.55 1.58,2.55, body extent -3.01,-2.45 3.01,2.45, height 1.57
DMM0022A [mm] "SON, 27-Leads, Body 5x6mm, Pitch 0.5mm"
  rrect40% 0.7x0.25 smd: 1(-2.35,2.5) 2(-2.35,2) 21(2.35,2) 22(2.35,2.5)
  rrect40% 0.7x0.25 smd mask+0: 3(-2.35,1.5) 4(-2.35,1) 5(-2.35,0.5) 6(-2.35,0) 7(-2.35,-0.5) 8(-2.35,-1) 9(-2.35,-1.5) 10(-2.35,-2) 11(-2.35,-2.5) 12(2.35,-2.5) 13(2.35,-2) 14(2.35,-1.5) 15(2.35,-1) 16(2.35,-0.5) 17(2.35,0) 18(2.35,0.5) 19(2.35,1) 20(2.35,1.5)
  rrect27% 0.43x0.375 smd: 23(-2.115,3.013) 24(-2.115,-3.013) 25(2.115,-3.013) 26(2.115,3.013)
  rrect3% 3.3x5.4 smd paste-1.65: 27(0,0)
  rrect9% 1.41x1.12 on Top Paste: ""(-0.805,1.98) ""(-0.805,-0.66) ""(-0.805,0.66) ""(-0.805,-1.98) ""(0.805,1.98) ""(0.805,-0.66) ""(0.805,0.66) ""(0.805,-1.98)
  Top Layer region: -2.3,-2.5 -2,-2.5 -2,1.5 -2.3,1.5
  Top Layer region: 2.3,1.5 2,1.5 2,-2.5 2.3,-2.5
  Top Layer region: -2.75,-2.575 -2.75,1.575 -2.742,1.613 -2.721,1.646 -2.688,1.667 -2.65,1.675 -2.65,1.675 -2.05,1.675 -2.012,1.667 -1.979,1.646 -1.958,1.613 -1.95,1.575 -1.95,1.575 -1.95,-2.575 -1.958,-2.613 -1.979,-2.646 -2.012,-2.667 -2.05,-2.675 -2.05,-2.675 -2.65,-2.675 -2.688,-2.667 -2.721,-2.646 -2.742,-2.613 -2.75,-2.575
  Top Layer region: 2.75,-2.575 2.75,1.575 2.742,1.613 2.721,1.646 2.688,1.667 2.65,1.675 2.65,1.675 2.05,1.675 2.012,1.667 1.979,1.646 1.958,1.613 1.95,1.575 1.95,1.575 1.95,-2.575 1.958,-2.613 1.979,-2.646 2.012,-2.667 2.05,-2.675 2.05,-2.675 2.65,-2.675 2.688,-2.667 2.721,-2.646 2.742,-2.613 2.75,-2.575
  silkscreen extent -1.6,-3.15 1.6,3.15, body extent -2.5,-3 2.5,3, height 1.05
DNH0008A [mm] "VSONP-8"
  rrect50% 0.7x0.4 smd paste-0.05 mask-0.05: 1(-1.55,0.975) 2(-1.55,0.325) 3(-1.55,-0.325) 4(-1.55,-0.975) 5(1.55,-0.975) 6(1.55,-0.325) 7(1.55,0.325) 8(1.55,0.975)
  rrect4% 2.51x2.55 smd paste-1.5 mask-1.5: 9(0.645,0)
  rrect14% 0.705x1.125 on Top Paste: 9A(-0.208,0.662) 9B(0.697,0.662) 9C(-0.208,-0.663) 9D(0.697,-0.663)
  silkscreen extent -1.62,-1.7 1.62,1.7, body extent -1.65,-1.65 1.65,1.66, height 0.91
DNK0008A [mm] "SON, 8-Leads, Body 5x6mm"
  rrect39% 0.86x0.51 smd paste-0.05 mask-0.05: 1(-2.82,1.905) 2(-2.82,0.635) 3(-2.82,-0.635) 4(-2.82,-1.905) 5(2.82,-1.905) 6(2.82,-0.635) 7(2.82,0.635) 8(2.82,1.905)
  rrect40% 0.25x0.555 on Top Solder: 9(-0.83,2.372) 9(-0.83,-2.372)
  rrect40% 0.25x0.555 on Top Paste: 9(-0.83,2.372) 9(-0.83,-2.372)
  rrect11% 0.95x1.13 on Top Paste: 9(-0.535,1.33) 9(-0.535,0) 9(-0.535,-1.33) 9(0.615,1.33) 9(0.615,0) 9(0.615,-1.33) 9(1.765,-1.33) 9(1.765,0) 9(1.765,1.33)
  rrect3% 3.58x4 on Top Solder: 9(0.75,0)
  rrect5% 4.34x5.4 smd paste-3 mask-3: 9(1.08,0)
  body extent -3.05,-2.55 3.05,2.55, height 1.06
DQN0004A [mm] "SON, 0.65mm pitch"
  rect 0.25x0.31 smd paste-1 mask-0.31: 1(-0.535,0.325) 2(-0.535,-0.325) 3(0.535,-0.325) 4(0.535,0.325)
  rect 0.58x0.58 smd rot 45 paste-0.065 mask-0.05: 5(0,0)
  Top Layer region: -0.66,-0.48 -0.2,-0.48 -0.2,-0.379 -0.409,-0.17 -0.66,-0.17
  Top Layer region: 0.66,-0.48 0.2,-0.48 0.2,-0.379 0.409,-0.17 0.66,-0.17
  Top Layer region: 0.66,0.48 0.2,0.48 0.2,0.379 0.409,0.17 0.66,0.17
  Top Layer region: -0.66,0.48 -0.2,0.48 -0.2,0.379 -0.409,0.17 -0.66,0.17
  silkscreen extent -0.88,-0.7 0.88,0.7, body extent -0.53,-0.53 0.53,0.53, height 0.42
DRB0008A [mm] "VSON-8"
  rrect32% 0.6x0.31 smd: 1(-1.4,0.975) 2(-1.4,0.325) 3(-1.4,-0.325) 4(-1.4,-0.975) 5(1.4,-0.975) 6(1.4,-0.325) 7(1.4,0.325) 8(1.4,0.975)
  rrect7% 1.5x1.75 smd paste-0.75: 9(0,0)
  Top Layer region: -0.7,-0.875 -0.49,-0.875 -0.471,-0.879 -0.455,-0.89 -0.444,-0.906 -0.44,-0.925 -0.44,-0.925 -0.44,-1.65 -0.436,-1.669 -0.425,-1.685 -0.409,-1.696 -0.39,-1.7 -0.39,-1.7 -0.26,-1.7 -0.241,-1.696 -0.225,-1.685 -0.214,-1.669 -0.21,-1.65 -0.21,-1.65 -0.21,-0.925 -0.206,-0.906 -0.195,-0.89 -0.179,-0.879 -0.16,-0.875 -0.16,-0.875 0.16,-0.875 0.179,-0.879 0.195,-0.89 0.206,-0.906 0.21,-0.925 0.21,-0.925 0.21,-1.65 0.21,-1.65 0.214,-1.669 0.225,-1.685 0.241,-1.696 0.26,-1.7 0.26,-1.7 0.39,-1.7 0.409,-1.696 0.425,-1.685 0.436,-1.669 0.44,-1.65 0.44,-1.65 0.44,-0.925 0.444,-0.906 0.455,-0.89 0.471,-0.879 0.49,-0.875 0.49,-0.875 0.7,-0.875 0.719,-0.871 0.735,-0.86 0.746,-0.844 0.75,-0.825 0.75,-0.825 0.75,0.825 0.746,0.844 0.735,0.86 0.719,0.871 0.7,0.875 0.7,0.875 0.49,0.875 0.471,0.879 0.455,0.89 0.444,0.906 0.44,0.925 0.44,0.925 0.44,1.65 0.436,1.669 0.425,1.685 0.409,1.696 0.39,1.7 0.39,1.7 0.26,1.7 0.241,1.696 0.225,1.685 0.214,1.669 0.21,1.65 0.21,1.65 0.21,1.65 0.21,0.925 0.206,0.906 0.195,0.89 0.179,0.879 0.16,0.875 0.16,0.875 -0.16,0.875 -0.179,0.879 -0.195,0.89 -0.206,0.906 -0.21,0.925 -0.21,0.925 -0.21,1.65 -0.214,1.669 -0.225,1.685 -0.241,1.696 -0.26,1.7 -0.26,1.7 -0.39,1.7 -0.409,1.696 -0.425,1.685 -0.436,1.669 -0.44,1.65 -0.44,1.65 -0.44,0.925 -0.444,0.906 -0.455,0.89 -0.471,0.879 -0.49,0.875 -0.49,0.875 -0.7,0.875 -0.719,0.871 -0.735,0.86 -0.746,0.844 -0.75,0.825 -0.75,0.825 -0.75,-0.825 -0.746,-0.844 -0.735,-0.86 -0.719,-0.871 -0.7,-0.875
  silkscreen extent -1.73,-1.73 1.73,1.73, body extent -1.5,-1.5 1.5,1.5, height 0.77
DSG0008A [mm] "SON, 8-Leads, Body 2x2mm, Pitch 0.5mm, Thermal Pad 1.6x0.9mm, TI Recommended"
  rrect40% 0.5x0.25 smd: 1(-0.95,0.75) 2(-0.95,0.25) 3(-0.95,-0.25) 4(-0.95,-0.75) 5(0.95,-0.75) 6(0.95,-0.25) 7(0.95,0.25) 8(0.95,0.75)
  rrect14% 0.9x0.7 on Top Paste: 9(0,0.45) 9(0,-0.45)
  rrect11% 0.9x1.6 smd paste-0.45: 9(0,0)
  silkscreen extent -1.07,-1.15 1.07,1.15, body extent -1,-1 1,1, height 0.77
FCC_disclaimer_stacked [mil]
Keystone5000 [mil] "For Keystone 500x miniature loop terminals"
  round 80 hole 40: 1(0,0)
  silkscreen extent -52,-52 52,52, body extent -49,-49 49,49, height 182
Keystone5001 [mil] "For Keystone 500x miniature loop terminals"
  round 80 hole 40: 1(0,0)
  silkscreen extent -52,-52 52,52, body extent -49,-49 49,49, height 182
Keystone5117 [mil] "For Keystone 500x miniature loop terminals"
  round 80 hole 40: 1(0,0)
  silkscreen extent -52,-52 52,52, body extent -49,-49 49,49, height 182
Keystone_1902C [mil] "Hex Standoff, 4-40 threaded, nylon"
  round 1 on Mech4: 0(0,0)
  body extent -145,-126 146,126, height 501
LED_LTST-C170_Red [mm] "LITE-ON"
  rect 1.2x1.2 smd: 1(-1.05,0) 2(1.05,0)
  silkscreen extent -1.6,-1 2.2,1, body extent -1.05,-0.67 1.05,0.67, height 1.1
LED_LTST-C171 [mm] "LITE-ON"
  rect 1.2x1.2 smd: 1(-1.05,0) 2(1.05,0)
  silkscreen extent -1.6,-1 2.2,1, body extent -1.05,-0.67 1.05,0.67, height 0.8
"NY PMS 440 0025 PH" [mm] "4-40 nylon screw and mounting hole"
  round 8 hole 3.2: 1(0,0)
  body extent -3.3,-3.3 3.3,3.3, height 2.69
On-Shore_ED120_2DS [mm] "ONSHORE"
  rrect5% 2x2 hole 1.25: 1(-2.54,0)
  round 2 hole 1.25: 2(2.54,0)
  silkscreen extent -5.6,-4 5.12,5, body extent -5.78,-4 5.08,5, height 13
Preci-dip_850-xx-004-10-001101 [mm] "Preci-dip"
  rect 1x1 hole 0.65: 1(-1.905,0)
  round 1 hole 0.65: 2(-0.635,0) 3(0.635,0) 4(1.905,0)
  silkscreen extent -3.32,-1.12 2.78,1.12, body extent -2.74,-1.1 2.74,1.1, height 5.2
PW0014A_N [mm] "TSOP, 14-Leads, Body 5x4.4mm, Pitch 0.65mm, IPC Medium Density"
  oval 1.4x0.45 smd: 1(-2.95,1.95) 2(-2.95,1.3) 3(-2.95,0.65) 4(-2.95,0) 5(-2.95,-0.65) 6(-2.95,-1.3) 7(-2.95,-1.95) 8(2.95,-1.95) 9(2.95,-1.3) 10(2.95,-0.65) 11(2.95,0) 12(2.95,0.65) 13(2.95,1.3) 14(2.95,1.95)
  silkscreen extent -3.4,-2.55 1.85,2.55, body extent -3.21,-2.5 3.21,2.5, height 1
PW0016A_N [mm] "TSOP, 16-Leads, Body 5x4.4mm, Pitch 0.65mm, IPC Medium Density"
  oval 1.4x0.45 smd: 1(-2.95,2.275) 2(-2.95,1.625) 3(-2.95,0.975) 4(-2.95,0.325) 5(-2.95,-0.325) 6(-2.95,-0.975) 7(-2.95,-1.625) 8(-2.95,-2.275) 9(2.95,-2.275) 10(2.95,-1.625) 11(2.95,-0.975) 12(2.95,-0.325) 13(2.95,0.325) 14(2.95,0.975) 15(2.95,1.625) 16(2.95,2.275)
  silkscreen extent -3.5,-2.55 1.85,2.75, body extent -3.21,-2.5 3.21,2.5, height 1
PWP0020A_N [mm] "TSOP, 20-Leads, Body 6.5x4.4mm, Pitch 0.65mm, Exposed Pad, IPC Medium Density"
  rrect22% 1.4x0.45 smd: 1(-2.95,2.925) 2(-2.95,2.275) 3(-2.95,1.625) 4(-2.95,0.975) 5(-2.95,0.325) 6(-2.95,-0.325) 7(-2.95,-0.975) 8(-2.95,-1.625) 9(-2.95,-2.275) 10(-2.95,-2.925) 11(2.95,-2.925) 12(2.95,-2.275) 13(2.95,-1.625) 14(2.95,-0.975) 15(2.95,-0.325) 16(2.95,0.325) 17(2.95,0.975) 18(2.95,1.625) 19(2.95,2.275) 20(2.95,2.925)
  rrect6% 3.4x6.5 smd paste-2 mask-2: 21(0,0)
  rrect3% 3.15x4.35 on Top Solder: 21(0,0)
  rrect3% 3.15x4.35 on Top Paste: 21(0,0)
  silkscreen extent -3.55,-3.3 1.5,3.4, body extent -3.21,-3.25 3.21,3.25, height 1
RGZ0048A [mm] "VQFN-48"
  rrect42% 0.6x0.24 smd: 1(-3.4,2.75) 2(-3.4,2.25) 3(-3.4,1.75) 4(-3.4,1.25) 5(-3.4,0.75) 6(-3.4,0.25) 7(-3.4,-0.25) 8(-3.4,-0.75) 9(-3.4,-1.25) 10(-3.4,-1.75) 11(-3.4,-2.25) 12(-3.4,-2.75) 25(3.4,-2.75) 26(3.4,-2.25) 27(3.4,-1.75) 28(3.4,-1.25) 29(3.4,-0.75) 30(3.4,-0.25) 31(3.4,0.25) 32(3.4,0.75) 33(3.4,1.25) 34(3.4,1.75) 35(3.4,2.25) 36(3.4,2.75)
  rrect42% 0.24x0.6 smd: 13(-2.75,-3.4) 14(-2.25,-3.4) 15(-1.75,-3.4) 16(-1.25,-3.4) 17(-0.75,-3.4) 18(-0.25,-3.4) 19(0.25,-3.4) 20(0.75,-3.4) 21(1.25,-3.4) 22(1.75,-3.4) 23(2.25,-3.4) 24(2.75,-3.4) 37(2.75,3.4) 38(2.25,3.4) 39(1.75,3.4) 40(1.25,3.4) 41(0.75,3.4) 42(0.25,3.4) 43(-0.25,3.4) 44(-0.75,3.4) 45(-1.25,3.4) 46(-1.75,3.4) 47(-2.25,3.4) 48(-2.75,3.4)
  rrect2% 5.15x5.15 smd paste-2.6: 49(0,0)
  body extent -3.5,-3.5 3.5,3.5, height 1
RHA0040E [mm] "QFN, 40-Leads, Body 6x6mm, Pitch 0.5mm, Thermal Pad 2.9x2.9mm, TI Recommended"
  oval 0.6x0.23 smd mask+0.07: 1(-2.9,2.25) 2(-2.9,1.75) 3(-2.9,1.25) 4(-2.9,0.75) 5(-2.9,0.25) 6(-2.9,-0.25) 7(-2.9,-0.75) 8(-2.9,-1.25) 9(-2.9,-1.75) 10(-2.9,-2.25) 21(2.9,-2.25) 22(2.9,-1.75) 23(2.9,-1.25) 24(2.9,-0.75) 25(2.9,-0.25) 26(2.9,0.25) 27(2.9,0.75) 28(2.9,1.25) 29(2.9,1.75) 30(2.9,2.25)
  oval 0.23x0.6 smd mask+0.07: 11(-2.25,-2.9) 12(-1.75,-2.9) 13(-1.25,-2.9) 14(-0.75,-2.9) 15(-0.25,-2.9) 16(0.25,-2.9) 17(0.75,-2.9) 18(1.25,-2.9) 19(1.75,-2.9) 20(2.25,-2.9) 31(2.25,2.9) 32(1.75,2.9) 33(1.25,2.9) 34(0.75,2.9) 35(0.25,2.9) 36(-0.25,2.9) 37(-0.75,2.9) 38(-1.25,2.9) 39(-1.75,2.9) 40(-2.25,2.9)
  rect 3.52x2.62 smd paste-1.747: 41(0,0)
  silkscreen extent -3.22,-3.22 3.22,3.22, body extent -3.08,-3.08 3.08,3.08, height 1.01
Samtec_SSQ-110-03-x-D [mm] "Receptacle, 2.54mm, 10x2, TH"
  rect 1.55x1.55 hole 1.02: 1(-11.43,1.27)
  round 1.55 hole 1.02: 2(-11.43,-1.27) 3(-8.89,1.27) 4(-8.89,-1.27) 5(-6.35,1.27) 6(-6.35,-1.27) 7(-3.81,1.27) 8(-3.81,-1.27) 9(-1.27,1.27) 10(-1.27,-1.27) 11(1.27,1.27) 12(1.27,-1.27) 13(3.81,1.27) 14(3.81,-1.27) 15(6.35,1.27) 16(6.35,-1.27) 17(8.89,1.27) 18(8.89,-1.27) 19(11.43,1.27) 20(11.43,-1.27)
  silkscreen extent -12.95,-2.48 12.95,3, body extent -12.95,-2.48 12.95,2.48, height 8.51
SM_RADIAL_F [mm] "8 x 10.2mm:  Panasonic F"
  rect 4x2 smd: 1(-3.55,0) 2(3.55,0)
  silkscreen extent -4.25,-4.25 4.25,4.25, body extent -4.25,-4.25 4.25,4.25, height 10.5
SOD-123F [mm] "NXP recommended land pattern"
  rect 1.2x1.2 smd paste-0.05: 1(-1.4,0) 2(1.4,0)
  silkscreen extent -2.64,-1.12 2.01,1.12, body extent -1.8,-0.85 1.8,0.85, height 1.2
SOD-123FL [mm] "Copied from SOD-123"
  rect 0.915x1.22 smd: 1(-1.637,0) 2(1.637,0)
  silkscreen extent -2.74,-1.16 1.68,1.16, body extent -1.9,-0.9 1.9,0.9, height 1
SOT-23 [mm] "SOT23, 3-Leads, Body 2.9x1.3mm, Pitch 0.95mm, Lead Span 2.5mm, IPC Medium Density"
  rrect50% 1x0.6 smd: 1(-1.2,0.95) 2(-1.2,-0.95) 3(1.2,0)
  silkscreen extent -1.62,-1.5 0.7,1.5, body extent -1.16,-1.45 1.21,1.45, height 1
TI_Stacked_Overlay_Small [mil]
  silkscreen extent -418,-98 418,98
TSW-103-07-G-S [mm] "Samtec 100mil, 1x3, 230 mil above insulator"
  rrect50% 1.65x1.65 hole 1.016: 1(-2.54,0)
  round 1.65 hole 1.016: 2(0,0) 3(2.54,0)
  body extent -3.81,-1.27 3.81,1.27, height 8.38
WE-MAPI_4020 [mm] "SMD, 2-Leads, Body 4.1x4.1mm"
  rect 0.98x3.7 smd: 1(-1.185,0) 2(1.185,0)
  silkscreen extent -2.15,-2.15 2.15,2.15, body extent -2.15,-2.15 2.15,2.15, height 2.1
WEEE_Minimum [mil] "WEEElie bin"
  silkscreen extent -95,-172 99,104
WURTH_61300211121 [mm] "Header, 2.54mm, 2x1, TH"
  rrect50% 1.65x1.65 hole 1.15: 1(-1.27,0)
  round 1.65 hole 1.15: 2(1.27,0)
  body extent -2.54,-1.27 2.54,1.27, height 8.54
Wurth_691236510003 [mm] "Terminal Block, 5.08mm, 3x1, R/A, TH"
  rrect50% 2.25x2.25 hole 1.5: 1(-5.08,0)
  round 2.25 hole 1.5: 2(0,0) 3(5.08,0)
  body extent -8.22,-5.5 7.62,5.85, height 18
XAL6060 [mm] "Coilcraft recommended land pattern Document 887-4 Revised 01/14/18"
  rrect7% 1.43x5.5 smd: 1(-2.019,0) 2(2.019,0)
  body extent -3.28,-3.38 3.28,3.38, height 6.11
XFL3012 [mm] "Coilcraft"
  rect 1.12x3.2 smd: 1(-1.11,0) 2(1.11,0)
  body extent -1.6,-1.6 1.6,1.6, height 1.3
YBG0006AJAN [mm] "DSBGA-6"
  round 0.23 smd paste-0.23 mask+0.032: A1(-0.2,0.4) A2(0.2,0.4) B1(-0.2,0) B2(0.2,0) C1(-0.2,-0.4) C2(0.2,-0.4)
  body extent -0.5,-0.75 0.5,0.75, height 0.5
